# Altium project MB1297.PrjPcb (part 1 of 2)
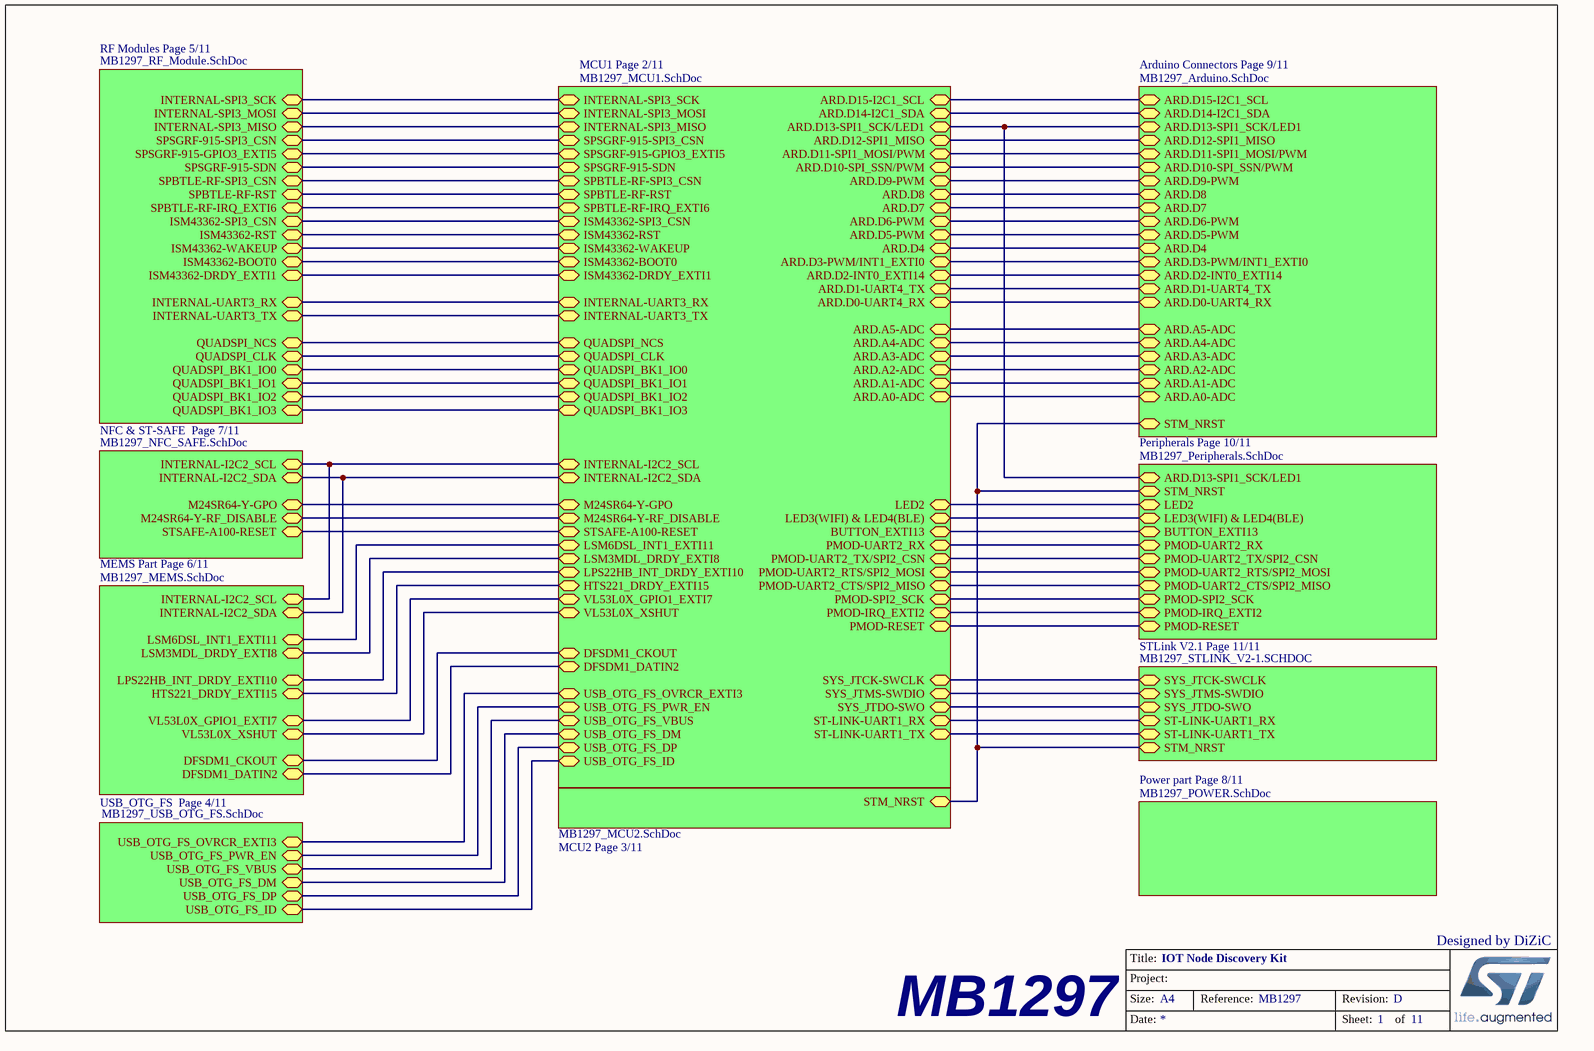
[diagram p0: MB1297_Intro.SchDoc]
11 sheets, 231 parts. Net scope: hierarchical (ports join the sheet entries above them; power ports are global).
Board file: MB1297.PcbDoc
Sheets:
  MB1297_Intro.SchDoc
    MCU1 Page 2/11 = MB1297_MCU1.SchDoc
    MCU2 Page 3/11 = MB1297_MCU2.SchDoc
    RF Modules Page 5/11 = MB1297_RF_Module.SchDoc
    Peripherals Page 10/11 = MB1297_Peripherals.SchDoc
    NFC & ST-SAFE  Page 7/11 = MB1297_NFC_SAFE.SchDoc
    STLink V2.1 Page 11/11 = MB1297_STLINK_V2-1.SCHDOC
    Arduino Connectors Page 9/11 = MB1297_Arduino.SchDoc
    MEMS Part Page 6/11 = MB1297_MEMS.SchDoc
    USB_OTG_FS  Page 4/11 = MB1297_USB_OTG_FS.SchDoc
    Power part Page 8/11 = MB1297_POWER.SchDoc

## Sheet MB1297_Intro.SchDoc: IOT Node Discovery Kit
size A4; DocumentNumber: MB1297; Revision: D; SheetNumber: 1; SheetTotal: 11

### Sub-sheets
Arduino Connectors Page 9/11 = MB1297_Arduino.SchDoc: ARD.D3-PWM/INT1_EXTI0, ARD.D2-INT0_EXTI14, ARD.D1-UART4_TX, ARD.D0-UART4_RX, ARD.A5-ADC, ARD.A4-ADC, ARD.A3-ADC, ARD.A2-ADC, ARD.A1-ADC, ARD.A0-ADC, ARD.D4, ARD.D5-PWM, ARD.D6-PWM, ARD.D7, ARD.D8, ARD.D9-PWM, ARD.D10-SPI_SSN/PWM, ARD.D11-SPI1_MOSI/PWM, ARD.D12-SPI1_MISO, ARD.D13-SPI1_SCK/LED1, ARD.D14-I2C1_SDA, ARD.D15-I2C1_SCL, STM_NRST
MCU1 Page 2/11 = MB1297_MCU1.SchDoc: INTERNAL-SPI3_SCK, INTERNAL-SPI3_MOSI, INTERNAL-SPI3_MISO, ISM43362-SPI3_CSN, SPSGRF-915-SDN, SPSGRF-915-SPI3_CSN, SPBTLE-RF-SPI3_CSN, SYS_JTCK-SWCLK, SYS_JTMS-SWDIO, ARD.D3-PWM/INT1_EXTI0, ARD.D2-INT0_EXTI14, ARD.D1-UART4_TX, ARD.D0-UART4_RX, ARD.D4, ARD.D5-PWM, ARD.D6-PWM, ARD.D7, ARD.D8, ARD.D9-PWM, ARD.D10-SPI_SSN/PWM, ARD.D11-SPI1_MOSI/PWM, ARD.D12-SPI1_MISO, ARD.D13-SPI1_SCK/LED1, ARD.D14-I2C1_SDA, ARD.D15-I2C1_SCL, ARD.A5-ADC, ARD.A4-ADC, ARD.A3-ADC, ARD.A2-ADC, ARD.A1-ADC, ARD.A0-ADC, USB_OTG_FS_OVRCR_EXTI3, USB_OTG_FS_PWR_EN, USB_OTG_FS_VBUS, USB_OTG_FS_DM, USB_OTG_FS_DP, USB_OTG_FS_ID, INTERNAL-I2C2_SCL, INTERNAL-I2C2_SDA, M24SR64-Y-GPO, M24SR64-Y-RF_DISABLE, STSAFE-A100-RESET, LED2, LED3(WIFI) & LED4(BLE), BUTTON_EXTI13, PMOD-UART2_RTS/SPI2_MOSI, PMOD-UART2_CTS/SPI2_MISO, PMOD-SPI2_SCK, PMOD-IRQ_EXTI2, PMOD-RESET, PMOD-UART2_RX, PMOD-UART2_TX/SPI2_CSN, LSM6DSL_INT1_EXTI11, LSM3MDL_DRDY_EXTI8, LPS22HB_INT_DRDY_EXTI10, HTS221_DRDY_EXTI15, VL53L0X_GPIO1_EXTI7, VL53L0X_XSHUT, DFSDM1_CKOUT, DFSDM1_DATIN2, SPBTLE-RF-RST, SYS_JTDO-SWO, QUADSPI_NCS, QUADSPI_CLK, QUADSPI_BK1_IO0, QUADSPI_BK1_IO1, QUADSPI_BK1_IO2, QUADSPI_BK1_IO3, SPSGRF-915-GPIO3_EXTI5, SPBTLE-RF-IRQ_EXTI6, ISM43362-DRDY_EXTI1, ISM43362-RST, ISM43362-WAKEUP, ISM43362-BOOT0, INTERNAL-UART3_RX, INTERNAL-UART3_TX, ST-LINK-UART1_RX, ST-LINK-UART1_TX
MCU2 Page 3/11 = MB1297_MCU2.SchDoc: STM_NRST
MEMS Part Page 6/11 = MB1297_MEMS.SchDoc: INTERNAL-I2C2_SCL, INTERNAL-I2C2_SDA, LSM6DSL_INT1_EXTI11, LSM3MDL_DRDY_EXTI8, LPS22HB_INT_DRDY_EXTI10, HTS221_DRDY_EXTI15, VL53L0X_GPIO1_EXTI7, VL53L0X_XSHUT, DFSDM1_CKOUT, DFSDM1_DATIN2
NFC & ST-SAFE  Page 7/11 = MB1297_NFC_SAFE.SchDoc: INTERNAL-I2C2_SCL, INTERNAL-I2C2_SDA, M24SR64-Y-GPO, M24SR64-Y-RF_DISABLE, STSAFE-A100-RESET
Peripherals Page 10/11 = MB1297_Peripherals.SchDoc: STM_NRST, ARD.D13-SPI1_SCK/LED1, LED2, LED3(WIFI) & LED4(BLE), BUTTON_EXTI13, PMOD-UART2_RTS/SPI2_MOSI, PMOD-UART2_CTS/SPI2_MISO, PMOD-SPI2_SCK, PMOD-IRQ_EXTI2, PMOD-RESET, PMOD-UART2_RX, PMOD-UART2_TX/SPI2_CSN
Power part Page 8/11 = MB1297_POWER.SchDoc: no entries
RF Modules Page 5/11 = MB1297_RF_Module.SchDoc: INTERNAL-SPI3_SCK, INTERNAL-SPI3_MOSI, INTERNAL-SPI3_MISO, SPSGRF-915-SPI3_CSN, SPSGRF-915-GPIO3_EXTI5, SPSGRF-915-SDN, SPBTLE-RF-SPI3_CSN, SPBTLE-RF-RST, SPBTLE-RF-IRQ_EXTI6, QUADSPI_NCS, QUADSPI_CLK, QUADSPI_BK1_IO0, QUADSPI_BK1_IO1, QUADSPI_BK1_IO2, QUADSPI_BK1_IO3, INTERNAL-UART3_RX, INTERNAL-UART3_TX, ISM43362-SPI3_CSN, ISM43362-RST, ISM43362-WAKEUP, ISM43362-BOOT0, ISM43362-DRDY_EXTI1
STLink V2.1 Page 11/11 = MB1297_STLINK_V2-1.SCHDOC: SYS_JTCK-SWCLK, SYS_JTMS-SWDIO, SYS_JTDO-SWO, ST-LINK-UART1_RX, ST-LINK-UART1_TX, STM_NRST
USB_OTG_FS  Page 4/11 = MB1297_USB_OTG_FS.SchDoc: USB_OTG_FS_OVRCR_EXTI3, USB_OTG_FS_PWR_EN, USB_OTG_FS_VBUS, USB_OTG_FS_DM, USB_OTG_FS_DP, USB_OTG_FS_ID

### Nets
USB_N: sheet MCU1 Page 2/11/USB_OTG_FS_DM, sheet USB_OTG_FS  Page 4/11/USB_OTG_FS_DM
USB_P: sheet MCU1 Page 2/11/USB_OTG_FS_DP, sheet USB_OTG_FS  Page 4/11/USB_OTG_FS_DP
NetC3_2: sheet MCU2 Page 3/11/STM_NRST, sheet Peripherals Page 10/11/STM_NRST, sheet STLink V2.1 Page 11/11/STM_NRST, sheet Arduino Connectors Page 9/11/STM_NRST
NetC66_1: sheet MCU1 Page 2/11/USB_OTG_FS_VBUS, sheet USB_OTG_FS  Page 4/11/USB_OTG_FS_VBUS
NetCN1_1: sheet MCU1 Page 2/11/ARD.D8, sheet Arduino Connectors Page 9/11/ARD.D8
NetCN1_2: sheet MCU1 Page 2/11/ARD.D9-PWM, sheet Arduino Connectors Page 9/11/ARD.D9-PWM
NetCN1_3: sheet MCU1 Page 2/11/ARD.D10-SPI_SSN/PWM, sheet Arduino Connectors Page 9/11/ARD.D10-SPI_SSN/PWM
NetCN1_4: sheet MCU1 Page 2/11/ARD.D11-SPI1_MOSI/PWM, sheet Arduino Connectors Page 9/11/ARD.D11-SPI1_MOSI/PWM
NetCN1_5: sheet MCU1 Page 2/11/ARD.D12-SPI1_MISO, sheet Arduino Connectors Page 9/11/ARD.D12-SPI1_MISO
NetCN1_6: sheet MCU1 Page 2/11/ARD.D13-SPI1_SCK/LED1, sheet Peripherals Page 10/11/ARD.D13-SPI1_SCK/LED1, sheet Arduino Connectors Page 9/11/ARD.D13-SPI1_SCK/LED1
NetCN1_9: sheet MCU1 Page 2/11/ARD.D14-I2C1_SDA, sheet Arduino Connectors Page 9/11/ARD.D14-I2C1_SDA
NetCN1_10: sheet MCU1 Page 2/11/ARD.D15-I2C1_SCL, sheet Arduino Connectors Page 9/11/ARD.D15-I2C1_SCL
NetCN3_1: sheet MCU1 Page 2/11/ARD.D0-UART4_RX, sheet Arduino Connectors Page 9/11/ARD.D0-UART4_RX
NetCN3_2: sheet MCU1 Page 2/11/ARD.D1-UART4_TX, sheet Arduino Connectors Page 9/11/ARD.D1-UART4_TX
NetCN3_3: sheet MCU1 Page 2/11/ARD.D2-INT0_EXTI14, sheet Arduino Connectors Page 9/11/ARD.D2-INT0_EXTI14
NetCN3_4: sheet MCU1 Page 2/11/ARD.D3-PWM/INT1_EXTI0, sheet Arduino Connectors Page 9/11/ARD.D3-PWM/INT1_EXTI0
NetCN3_5: sheet MCU1 Page 2/11/ARD.D4, sheet Arduino Connectors Page 9/11/ARD.D4
NetCN3_6: sheet MCU1 Page 2/11/ARD.D5-PWM, sheet Arduino Connectors Page 9/11/ARD.D5-PWM
NetCN3_7: sheet MCU1 Page 2/11/ARD.D6-PWM, sheet Arduino Connectors Page 9/11/ARD.D6-PWM
NetCN3_8: sheet MCU1 Page 2/11/ARD.D7, sheet Arduino Connectors Page 9/11/ARD.D7
NetCN4_1: sheet MCU1 Page 2/11/ARD.A0-ADC, sheet Arduino Connectors Page 9/11/ARD.A0-ADC
NetCN4_2: sheet MCU1 Page 2/11/ARD.A1-ADC, sheet Arduino Connectors Page 9/11/ARD.A1-ADC
NetCN4_3: sheet MCU1 Page 2/11/ARD.A2-ADC, sheet Arduino Connectors Page 9/11/ARD.A2-ADC
NetCN4_4: sheet MCU1 Page 2/11/ARD.A3-ADC, sheet Arduino Connectors Page 9/11/ARD.A3-ADC
NetCN4_5: sheet MCU1 Page 2/11/ARD.A4-ADC, sheet Arduino Connectors Page 9/11/ARD.A4-ADC
NetCN4_6: sheet MCU1 Page 2/11/ARD.A5-ADC, sheet Arduino Connectors Page 9/11/ARD.A5-ADC
NetCN9_4: sheet MCU1 Page 2/11/USB_OTG_FS_ID, sheet USB_OTG_FS  Page 4/11/USB_OTG_FS_ID
NetCN10_7: sheet MCU1 Page 2/11/PMOD-IRQ_EXTI2, sheet Peripherals Page 10/11/PMOD-IRQ_EXTI2
NetCN10_8: sheet MCU1 Page 2/11/PMOD-RESET, sheet Peripherals Page 10/11/PMOD-RESET
NetM1_4: sheet MCU1 Page 2/11/SPBTLE-RF-IRQ_EXTI6, sheet RF Modules Page 5/11/SPBTLE-RF-IRQ_EXTI6
NetM1_7: sheet MCU1 Page 2/11/INTERNAL-SPI3_SCK, sheet RF Modules Page 5/11/INTERNAL-SPI3_SCK
NetM1_8: sheet MCU1 Page 2/11/INTERNAL-SPI3_MISO, sheet RF Modules Page 5/11/INTERNAL-SPI3_MISO
NetM1_9: sheet MCU1 Page 2/11/INTERNAL-SPI3_MOSI, sheet RF Modules Page 5/11/INTERNAL-SPI3_MOSI
NetM1_10: sheet MCU1 Page 2/11/SPBTLE-RF-SPI3_CSN, sheet RF Modules Page 5/11/SPBTLE-RF-SPI3_CSN
NetM1_11: sheet MCU1 Page 2/11/SPBTLE-RF-RST, sheet RF Modules Page 5/11/SPBTLE-RF-RST
NetM2_12: sheet MCU1 Page 2/11/ISM43362-SPI3_CSN, sheet RF Modules Page 5/11/ISM43362-SPI3_CSN
NetM2_13: sheet MCU1 Page 2/11/ISM43362-DRDY_EXTI1, sheet RF Modules Page 5/11/ISM43362-DRDY_EXTI1
NetM2_16: sheet MCU1 Page 2/11/ISM43362-WAKEUP, sheet RF Modules Page 5/11/ISM43362-WAKEUP
NetM2_21: sheet MCU1 Page 2/11/INTERNAL-UART3_TX, sheet RF Modules Page 5/11/INTERNAL-UART3_TX
NetM2_22: sheet MCU1 Page 2/11/INTERNAL-UART3_RX, sheet RF Modules Page 5/11/INTERNAL-UART3_RX
NetM2_33: sheet MCU1 Page 2/11/ISM43362-BOOT0, sheet RF Modules Page 5/11/ISM43362-BOOT0
NetM2_34: sheet MCU1 Page 2/11/ISM43362-RST, sheet RF Modules Page 5/11/ISM43362-RST
NetM3_1: sheet MCU1 Page 2/11/SPSGRF-915-GPIO3_EXTI5, sheet RF Modules Page 5/11/SPSGRF-915-GPIO3_EXTI5
NetM3_10: sheet MCU1 Page 2/11/SPSGRF-915-SPI3_CSN, sheet RF Modules Page 5/11/SPSGRF-915-SPI3_CSN
NetM3_11: sheet MCU1 Page 2/11/SPSGRF-915-SDN, sheet RF Modules Page 5/11/SPSGRF-915-SDN
NetR1_2: sheet MCU1 Page 2/11/M24SR64-Y-RF_DISABLE, sheet NFC & ST-SAFE  Page 7/11/M24SR64-Y-RF_DISABLE
NetR4_2: sheet MCU1 Page 2/11/M24SR64-Y-GPO, sheet NFC & ST-SAFE  Page 7/11/M24SR64-Y-GPO
NetR6_2: sheet MCU1 Page 2/11/DFSDM1_CKOUT, sheet MEMS Part Page 6/11/DFSDM1_CKOUT
NetR10_2: sheet MCU1 Page 2/11/INTERNAL-I2C2_SCL, sheet NFC & ST-SAFE  Page 7/11/INTERNAL-I2C2_SCL, sheet MEMS Part Page 6/11/INTERNAL-I2C2_SCL
NetR11_2: sheet MCU1 Page 2/11/INTERNAL-I2C2_SDA, sheet NFC & ST-SAFE  Page 7/11/INTERNAL-I2C2_SDA, sheet MEMS Part Page 6/11/INTERNAL-I2C2_SDA
NetR13_2: sheet MCU1 Page 2/11/DFSDM1_DATIN2, sheet MEMS Part Page 6/11/DFSDM1_DATIN2
NetR14_2: sheet MCU1 Page 2/11/VL53L0X_GPIO1_EXTI7, sheet MEMS Part Page 6/11/VL53L0X_GPIO1_EXTI7
NetR15_2: sheet MCU1 Page 2/11/VL53L0X_XSHUT, sheet MEMS Part Page 6/11/VL53L0X_XSHUT
NetR20_1: sheet MCU1 Page 2/11/LED2, sheet Peripherals Page 10/11/LED2
NetR21_1: sheet MCU1 Page 2/11/LED3(WIFI) & LED4(BLE), sheet Peripherals Page 10/11/LED3(WIFI) & LED4(BLE)
NetR32_2: sheet MCU1 Page 2/11/SYS_JTCK-SWCLK, sheet STLink V2.1 Page 11/11/SYS_JTCK-SWCLK
NetR33_2: sheet MCU1 Page 2/11/SYS_JTMS-SWDIO, sheet STLink V2.1 Page 11/11/SYS_JTMS-SWDIO
NetR35_2: sheet MCU1 Page 2/11/SYS_JTDO-SWO, sheet STLink V2.1 Page 11/11/SYS_JTDO-SWO
NetR42_2: sheet MCU1 Page 2/11/ST-LINK-UART1_RX, sheet STLink V2.1 Page 11/11/ST-LINK-UART1_RX
NetR43_2: sheet MCU1 Page 2/11/ST-LINK-UART1_TX, sheet STLink V2.1 Page 11/11/ST-LINK-UART1_TX
NetR56_1: sheet MCU1 Page 2/11/USB_OTG_FS_OVRCR_EXTI3, sheet USB_OTG_FS  Page 4/11/USB_OTG_FS_OVRCR_EXTI3
NetR62_2: sheet MCU1 Page 2/11/USB_OTG_FS_PWR_EN, sheet USB_OTG_FS  Page 4/11/USB_OTG_FS_PWR_EN
NetSB3_1: sheet MCU1 Page 2/11/BUTTON_EXTI13, sheet Peripherals Page 10/11/BUTTON_EXTI13
NetSB12_2: sheet MCU1 Page 2/11/PMOD-UART2_TX/SPI2_CSN, sheet Peripherals Page 10/11/PMOD-UART2_TX/SPI2_CSN
NetSB15_2: sheet MCU1 Page 2/11/PMOD-UART2_RTS/SPI2_MOSI, sheet Peripherals Page 10/11/PMOD-UART2_RTS/SPI2_MOSI
NetSB18_2: sheet MCU1 Page 2/11/PMOD-UART2_CTS/SPI2_MISO, sheet Peripherals Page 10/11/PMOD-UART2_CTS/SPI2_MISO
NetSB20_1: sheet MCU1 Page 2/11/PMOD-UART2_RX, sheet Peripherals Page 10/11/PMOD-UART2_RX
NetSB21_1: sheet MCU1 Page 2/11/PMOD-SPI2_SCK, sheet Peripherals Page 10/11/PMOD-SPI2_SCK
NetU1_41: sheet MCU1 Page 2/11/QUADSPI_CLK, sheet RF Modules Page 5/11/QUADSPI_CLK
NetU1_42: sheet MCU1 Page 2/11/QUADSPI_NCS, sheet RF Modules Page 5/11/QUADSPI_NCS
NetU1_43: sheet MCU1 Page 2/11/QUADSPI_BK1_IO0, sheet RF Modules Page 5/11/QUADSPI_BK1_IO0
NetU1_44: sheet MCU1 Page 2/11/QUADSPI_BK1_IO1, sheet RF Modules Page 5/11/QUADSPI_BK1_IO1
NetU1_45: sheet MCU1 Page 2/11/QUADSPI_BK1_IO2, sheet RF Modules Page 5/11/QUADSPI_BK1_IO2
NetU1_46: sheet MCU1 Page 2/11/QUADSPI_BK1_IO3, sheet RF Modules Page 5/11/QUADSPI_BK1_IO3
NetU1_57: sheet MCU1 Page 2/11/LPS22HB_INT_DRDY_EXTI10, sheet MEMS Part Page 6/11/LPS22HB_INT_DRDY_EXTI10
NetU1_58: sheet MCU1 Page 2/11/LSM6DSL_INT1_EXTI11, sheet MEMS Part Page 6/11/LSM6DSL_INT1_EXTI11
NetU1_62: sheet MCU1 Page 2/11/HTS221_DRDY_EXTI15, sheet MEMS Part Page 6/11/HTS221_DRDY_EXTI15
NetU1_65: sheet MCU1 Page 2/11/LSM3MDL_DRDY_EXTI8, sheet MEMS Part Page 6/11/LSM3MDL_DRDY_EXTI8
NetU1_88: sheet MCU1 Page 2/11/STSAFE-A100-RESET, sheet NFC & ST-SAFE  Page 7/11/STSAFE-A100-RESET

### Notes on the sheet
- Designed by DiZiC
- MB1297

## Sheet MB1297_MCU1.SchDoc: STM32L475 - 1/2
size A4; DocumentNumber: MB1297; Revision: D; SheetNumber: 2; SheetTotal: 11
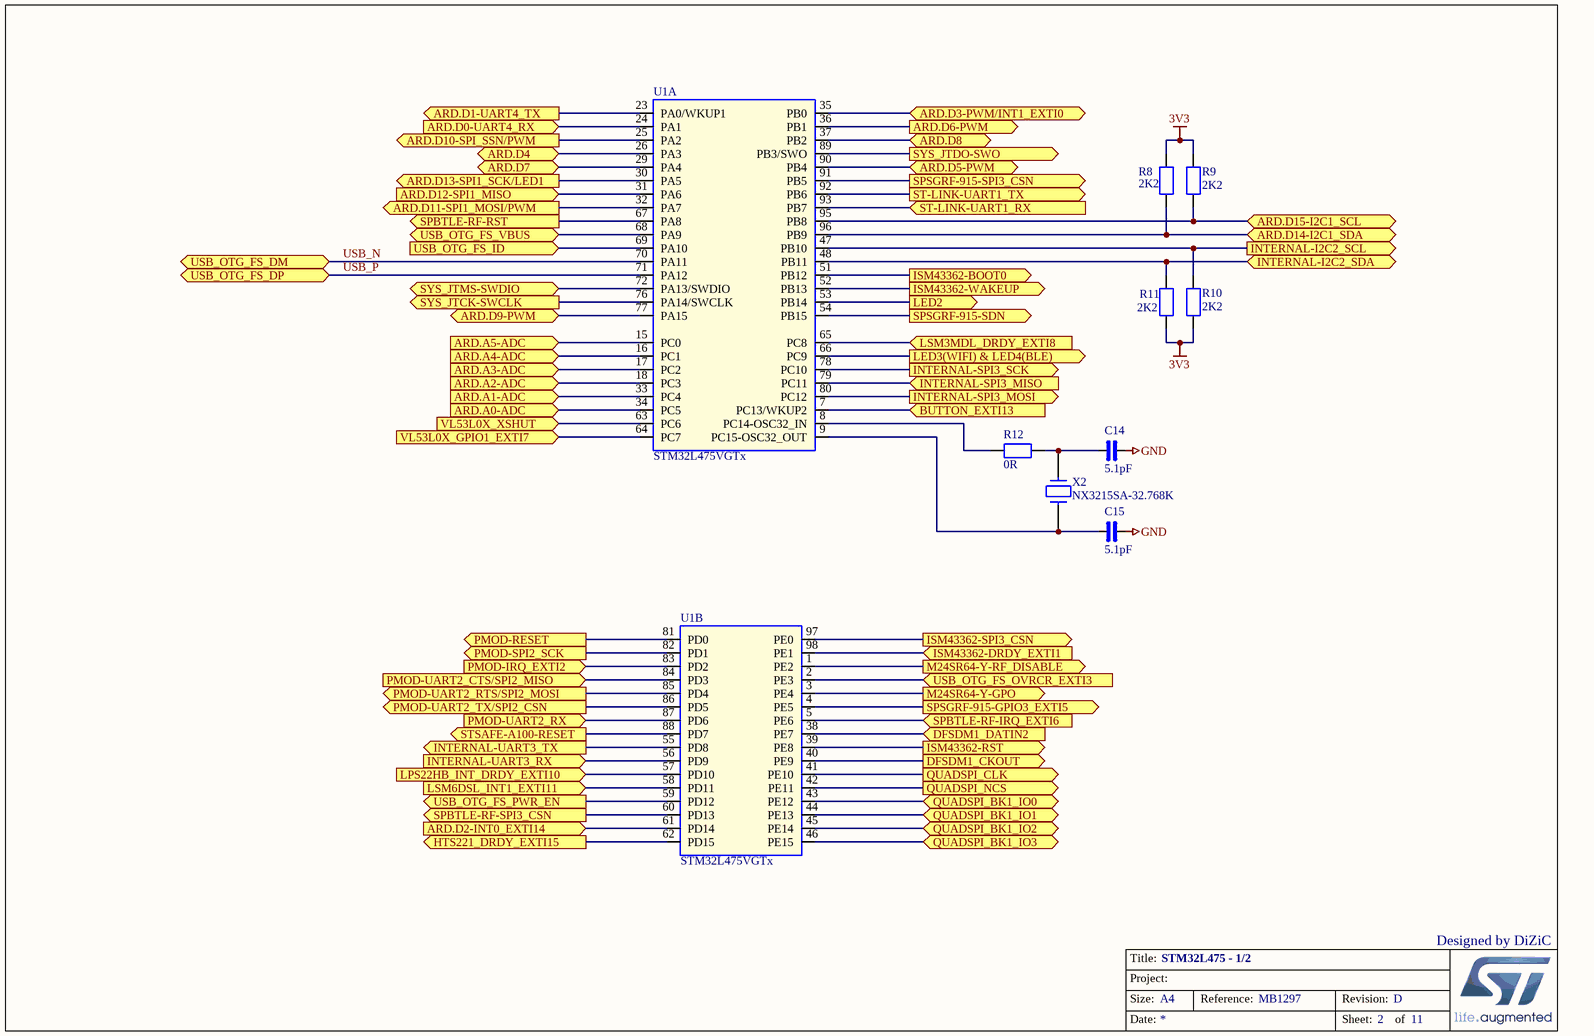
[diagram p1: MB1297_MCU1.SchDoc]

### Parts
C14  5.1pF  [0402_CAP_NPOL]
C15  5.1pF  [0402_CAP_NPOL]
R8  2K2  [0402_RES]
R9  2K2  [0402_RES]
R10  2K2  [0402_RES]
R11  2K2  [0402_RES]
R12  0R  [0402_RES]
U1  STM32L475VGTx  [LQFP100 14x14x1.6]  (parts A,B of 3)
X2  NX3215SA-32.768K  [CRY_NX3215SA_2P]

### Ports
ARD.A0-ADC, ARD.A1-ADC, ARD.A2-ADC, ARD.A3-ADC, ARD.A4-ADC, ARD.A5-ADC, ARD.D0-UART4_RX, ARD.D1-UART4_TX, ARD.D2-INT0_EXTI14, ARD.D3-PWM/INT1_EXTI0, ARD.D4, ARD.D5-PWM, ARD.D6-PWM, ARD.D7, ARD.D8, ARD.D9-PWM, ARD.D10-SPI_SSN/PWM, ARD.D11-SPI1_MOSI/PWM, ARD.D12-SPI1_MISO, ARD.D13-SPI1_SCK/LED1, ARD.D14-I2C1_SDA, ARD.D15-I2C1_SCL, BUTTON_EXTI13, DFSDM1_CKOUT, DFSDM1_DATIN2, HTS221_DRDY_EXTI15, INTERNAL-I2C2_SCL, INTERNAL-I2C2_SDA, INTERNAL-SPI3_MISO, INTERNAL-SPI3_MOSI, INTERNAL-SPI3_SCK, INTERNAL-UART3_RX, INTERNAL-UART3_TX, ISM43362-BOOT0, ISM43362-DRDY_EXTI1, ISM43362-RST, ISM43362-SPI3_CSN, ISM43362-WAKEUP, LED2, LED3(WIFI) & LED4(BLE), LPS22HB_INT_DRDY_EXTI10, LSM3MDL_DRDY_EXTI8, LSM6DSL_INT1_EXTI11, M24SR64-Y-GPO, M24SR64-Y-RF_DISABLE, PMOD-IRQ_EXTI2, PMOD-RESET, PMOD-SPI2_SCK, PMOD-UART2_CTS/SPI2_MISO, PMOD-UART2_RTS/SPI2_MOSI, PMOD-UART2_RX, PMOD-UART2_TX/SPI2_CSN, QUADSPI_BK1_IO0, QUADSPI_BK1_IO1, QUADSPI_BK1_IO2, QUADSPI_BK1_IO3, QUADSPI_CLK, QUADSPI_NCS, SPBTLE-RF-IRQ_EXTI6, SPBTLE-RF-RST, SPBTLE-RF-SPI3_CSN, SPSGRF-915-GPIO3_EXTI5, SPSGRF-915-SDN, SPSGRF-915-SPI3_CSN, ST-LINK-UART1_RX, ST-LINK-UART1_TX, STSAFE-A100-RESET, SYS_JTCK-SWCLK, SYS_JTDO-SWO, SYS_JTMS-SWDIO, USB_OTG_FS_DM, USB_OTG_FS_DP, USB_OTG_FS_ID, USB_OTG_FS_OVRCR_EXTI3, USB_OTG_FS_PWR_EN, USB_OTG_FS_VBUS, VL53L0X_GPIO1_EXTI7, VL53L0X_XSHUT

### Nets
3V3: R8.1 R9.1 R10.1 R11.1
GND: C14.2 C15.2
USB_N: U1.70(PA11) ; port USB_OTG_FS_DM
USB_P: U1.71(PA12) ; port USB_OTG_FS_DP
NetC14_1: C14.1 R12.2 X2.1
NetC15_1: C15.1 U1.9(PC15-OSC32_OUT) X2.2
NetC66_1: U1.68(PA9) ; port USB_OTG_FS_VBUS
NetCN1_1: U1.37(PB2) ; port ARD.D8
NetCN1_2: U1.77(PA15) ; port ARD.D9-PWM
NetCN1_3: U1.25(PA2) ; port ARD.D10-SPI_SSN/PWM
NetCN1_4: U1.32(PA7) ; port ARD.D11-SPI1_MOSI/PWM
NetCN1_5: U1.31(PA6) ; port ARD.D12-SPI1_MISO
NetCN1_6: U1.30(PA5) ; port ARD.D13-SPI1_SCK/LED1
NetCN1_9: R8.2 U1.96(PB9) ; port ARD.D14-I2C1_SDA
NetCN1_10: R9.2 U1.95(PB8) ; port ARD.D15-I2C1_SCL
NetCN3_1: U1.24(PA1) ; port ARD.D0-UART4_RX
NetCN3_2: U1.23(PA0/WKUP1) ; port ARD.D1-UART4_TX
NetCN3_3: U1.61(PD14) ; port ARD.D2-INT0_EXTI14
NetCN3_4: U1.35(PB0) ; port ARD.D3-PWM/INT1_EXTI0
NetCN3_5: U1.26(PA3) ; port ARD.D4
NetCN3_6: U1.90(PB4) ; port ARD.D5-PWM
NetCN3_7: U1.36(PB1) ; port ARD.D6-PWM
NetCN3_8: U1.29(PA4) ; port ARD.D7
NetCN4_1: U1.34(PC5) ; port ARD.A0-ADC
NetCN4_2: U1.33(PC4) ; port ARD.A1-ADC
NetCN4_3: U1.18(PC3) ; port ARD.A2-ADC
NetCN4_4: U1.17(PC2) ; port ARD.A3-ADC
NetCN4_5: U1.16(PC1) ; port ARD.A4-ADC
NetCN4_6: U1.15(PC0) ; port ARD.A5-ADC
NetCN9_4: U1.69(PA10) ; port USB_OTG_FS_ID
NetCN10_7: U1.83(PD2) ; port PMOD-IRQ_EXTI2
NetCN10_8: U1.81(PD0) ; port PMOD-RESET
NetM1_4: U1.5(PE6) ; port SPBTLE-RF-IRQ_EXTI6
NetM1_7: U1.78(PC10) ; port INTERNAL-SPI3_SCK
NetM1_8: U1.79(PC11) ; port INTERNAL-SPI3_MISO
NetM1_9: U1.80(PC12) ; port INTERNAL-SPI3_MOSI
NetM1_10: U1.60(PD13) ; port SPBTLE-RF-SPI3_CSN
NetM1_11: U1.67(PA8) ; port SPBTLE-RF-RST
NetM2_12: U1.97(PE0) ; port ISM43362-SPI3_CSN
NetM2_13: U1.98(PE1) ; port ISM43362-DRDY_EXTI1
NetM2_16: U1.52(PB13) ; port ISM43362-WAKEUP
NetM2_21: U1.55(PD8) ; port INTERNAL-UART3_TX
NetM2_22: U1.56(PD9) ; port INTERNAL-UART3_RX
NetM2_33: U1.51(PB12) ; port ISM43362-BOOT0
NetM2_34: U1.39(PE8) ; port ISM43362-RST
NetM3_1: U1.4(PE5) ; port SPSGRF-915-GPIO3_EXTI5
NetM3_10: U1.91(PB5) ; port SPSGRF-915-SPI3_CSN
NetM3_11: U1.54(PB15) ; port SPSGRF-915-SDN
NetR1_2: U1.1(PE2) ; port M24SR64-Y-RF_DISABLE
NetR4_2: U1.3(PE4) ; port M24SR64-Y-GPO
NetR6_2: U1.40(PE9) ; port DFSDM1_CKOUT
NetR10_2: R10.2 U1.47(PB10) ; port INTERNAL-I2C2_SCL
NetR11_2: R11.2 U1.48(PB11) ; port INTERNAL-I2C2_SDA
NetR12_1: R12.1 U1.8(PC14-OSC32_IN)
NetR13_2: U1.38(PE7) ; port DFSDM1_DATIN2
NetR14_2: U1.64(PC7) ; port VL53L0X_GPIO1_EXTI7
NetR15_2: U1.63(PC6) ; port VL53L0X_XSHUT
NetR20_1: U1.53(PB14) ; port LED2
NetR21_1: U1.66(PC9) ; port LED3(WIFI) & LED4(BLE)
NetR32_2: U1.76(PA14/SWCLK) ; port SYS_JTCK-SWCLK
NetR33_2: U1.72(PA13/SWDIO) ; port SYS_JTMS-SWDIO
NetR35_2: U1.89(PB3/SWO) ; port SYS_JTDO-SWO
NetR42_2: U1.93(PB7) ; port ST-LINK-UART1_RX
NetR43_2: U1.92(PB6) ; port ST-LINK-UART1_TX
NetR56_1: U1.2(PE3) ; port USB_OTG_FS_OVRCR_EXTI3
NetR62_2: U1.59(PD12) ; port USB_OTG_FS_PWR_EN
NetSB3_1: U1.7(PC13/WKUP2) ; port BUTTON_EXTI13
NetSB12_2: U1.86(PD5) ; port PMOD-UART2_TX/SPI2_CSN
NetSB15_2: U1.85(PD4) ; port PMOD-UART2_RTS/SPI2_MOSI
NetSB18_2: U1.84(PD3) ; port PMOD-UART2_CTS/SPI2_MISO
NetSB20_1: U1.87(PD6) ; port PMOD-UART2_RX
NetSB21_1: U1.82(PD1) ; port PMOD-SPI2_SCK
NetU1_41: U1.41(PE10) ; port QUADSPI_CLK
NetU1_42: U1.42(PE11) ; port QUADSPI_NCS
NetU1_43: U1.43(PE12) ; port QUADSPI_BK1_IO0
NetU1_44: U1.44(PE13) ; port QUADSPI_BK1_IO1
NetU1_45: U1.45(PE14) ; port QUADSPI_BK1_IO2
NetU1_46: U1.46(PE15) ; port QUADSPI_BK1_IO3
NetU1_57: U1.57(PD10) ; port LPS22HB_INT_DRDY_EXTI10
NetU1_58: U1.58(PD11) ; port LSM6DSL_INT1_EXTI11
NetU1_62: U1.62(PD15) ; port HTS221_DRDY_EXTI15
NetU1_65: U1.65(PC8) ; port LSM3MDL_DRDY_EXTI8
NetU1_88: U1.88(PD7) ; port STSAFE-A100-RESET

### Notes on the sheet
- Designed by DiZiC

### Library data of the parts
C14 C15 = CAP_NPOL: Capacitor_not polarized
R8-R12 = RES: Resistor
X2 = XTAL_32K_NX3215SA: Crystal 32.768kHz, 6pF, -+20PPM, R=50K, SMD; Manuf_1: NDK; Manuf_Part_1: NX3215SA 32.768KHz EXS00A-MU00525; ECCN_US/EU: EAR99/NEC; Ref St: 9157034; NDK Ref: X3101802; Fitted: YES; Ordered_By: STM

## Sheet MB1297_MCU2.SchDoc: STM32L475 - 2/2
size A4; DocumentNumber: MB1297; Revision: D; SheetNumber: 3; SheetTotal: 11
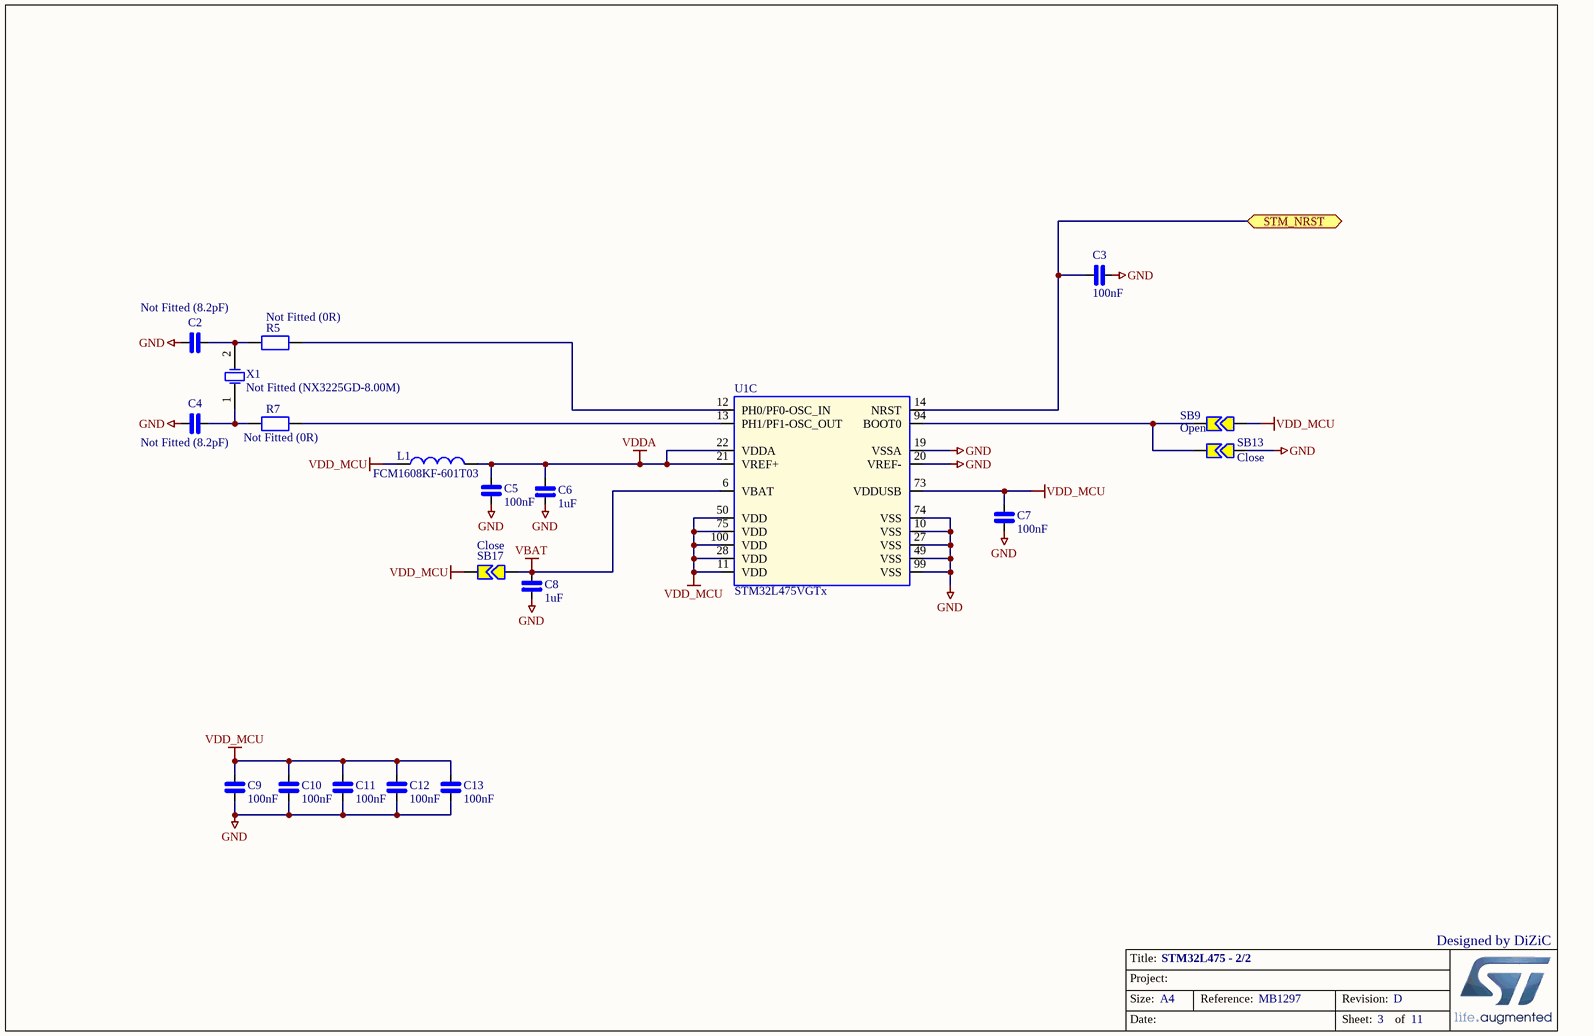
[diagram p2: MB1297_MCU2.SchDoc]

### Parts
C2  Not Fitted (8.2pF)  [0402_CAP_NPOL]
C3  100nF  [0402_CAP_NPOL]
C4  Not Fitted (8.2pF)  [0402_CAP_NPOL]
C5  100nF  [0402_CAP_NPOL]
C6  1uF  [0402_CAP_NPOL]
C7  100nF  [0402_CAP_NPOL]
C8  1uF  [0402_CAP_NPOL]
C9  100nF  [0402_CAP_NPOL]
C10  100nF  [0402_CAP_NPOL]
C11  100nF  [0402_CAP_NPOL]
C12  100nF  [0402_CAP_NPOL]
C13  100nF  [0402_CAP_NPOL]
L1  FCM1608KF-601T03  [0603L]
R5  Not Fitted (0R)  [0402_RES]
R7  Not Fitted (0R)  [0402_RES]
SB9  Open  [SB]
SB13  Close  [SB]
SB17  Close  [SB]
U1  STM32L475VGTx  [LQFP100 14x14x1.6]  (part C of 3)
X1  Not Fitted (NX3225GD-8.00M)  [CRY_NX3225GD_2P]

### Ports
STM_NRST

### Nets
GND: C2.2 C3.1 C4.2 C5.2 C6.1 C7.2 C8.1 C9.2 C10.2 C11.2 C12.2 C13.2 SB13.1 U1.10(VSS) U1.19(VSSA) U1.20(VREF-) U1.27(VSS) U1.49(VSS) U1.74(VSS) U1.99(VSS)
VBAT: C8.2 SB17.2 U1.6(VBAT)
VDD_MCU: C7.1 C9.1 C10.1 C11.1 C12.1 C13.1 L1.1 SB9.1 SB17.1 U1.11(VDD) U1.28(VDD) U1.50(VDD) U1.73(VDDUSB) U1.75(VDD) U1.100(VDD)
VDDA: C5.1 C6.2 L1.2 U1.21(VREF+) U1.22(VDDA)
NetC2_1: C2.1 R5.2 X1.2(OSC2)
NetC3_2: C3.2 U1.14(NRST) ; port STM_NRST
NetC4_1: C4.1 R7.2 X1.1(OSC1)
NetR5_1: R5.1 U1.12(PH0/PF0-OSC_IN)
NetR7_1: R7.1 U1.13(PH1/PF1-OSC_OUT)
NetSB9_2: SB9.2 SB13.2 U1.94(BOOT0)

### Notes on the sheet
- Designed by DiZiC

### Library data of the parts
C2-C13 = CAP_NPOL: Capacitor_not polarized
L1 = Inductor: Value: 100uH
R5 R7 = RES: Resistor; FITTED: NO
SB9 SB13 SB17 = Strap2: Solder Jumper; Solder: YES
X1 = XTAL_8M_NX3225GD: Crystal 8Mhz, 8pF, -+50PPM, SMD; Manuf_1: NDK; Manuf_Part_1: NX3225GD 8MHz EXS00A-CG04874; ECCN_US/EU: EAR99/NEC; NDK Ref: X3127326; Ref St: 9157029; Fitted: NO; Ordered_By: STM

## Sheet MB1297_RF_Module.SchDoc: RF Modules
size A4; DocumentNumber: MB1297; Revision: D; SheetNumber: 5; SheetTotal: 11
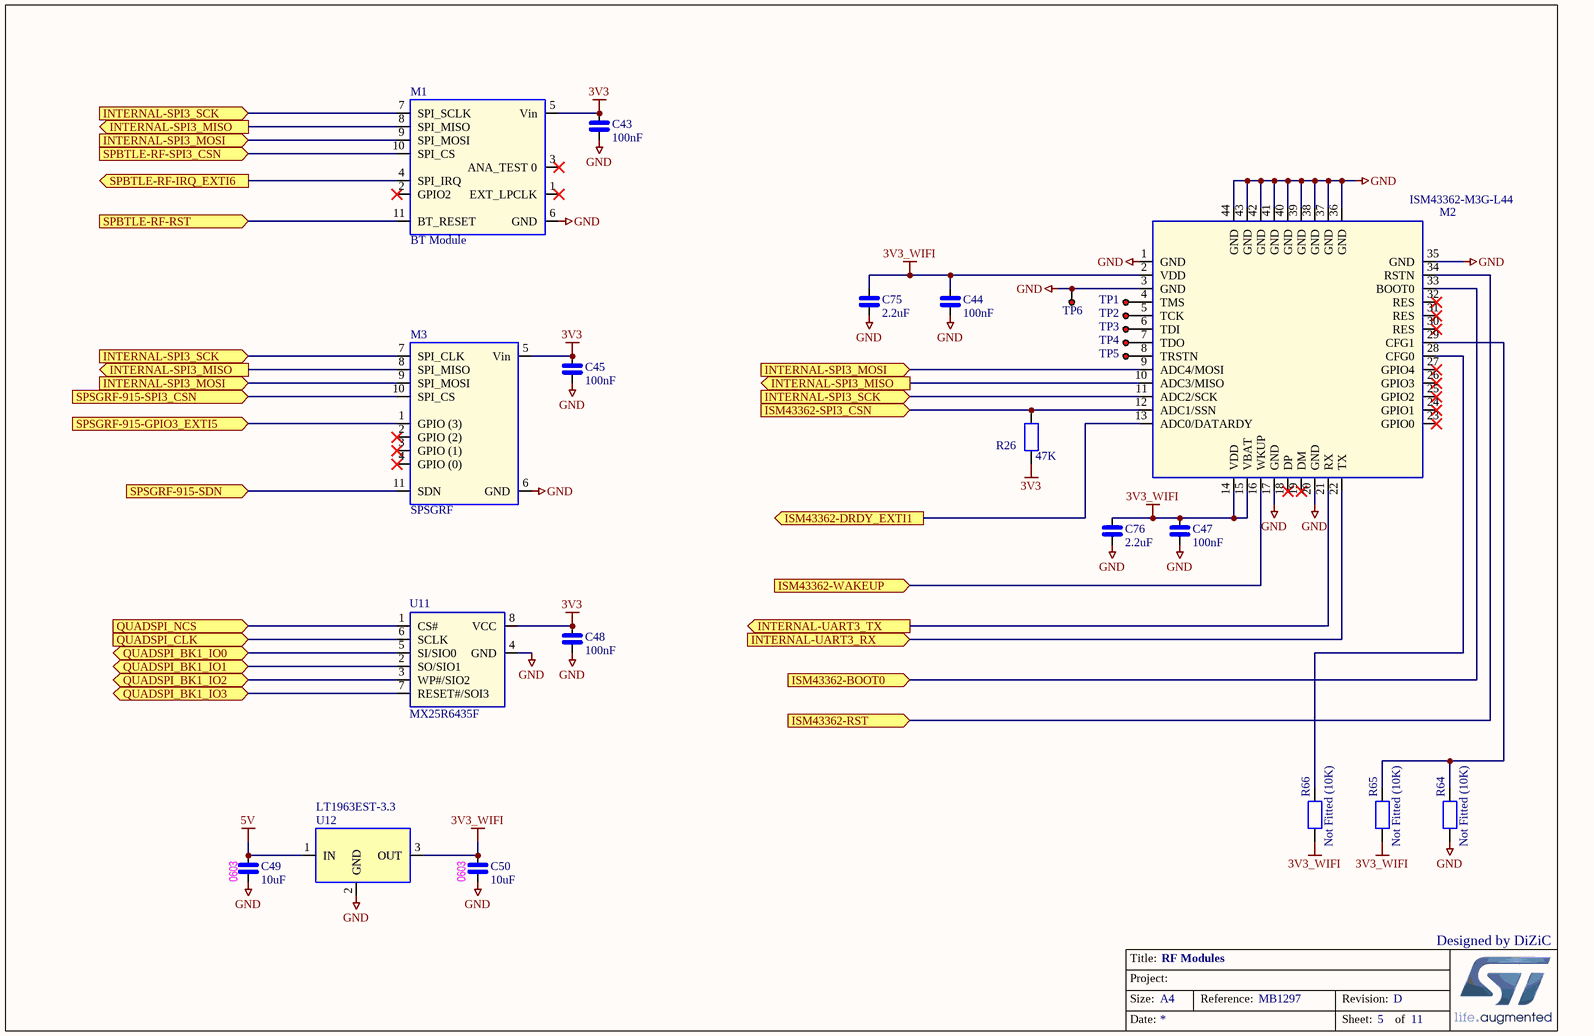
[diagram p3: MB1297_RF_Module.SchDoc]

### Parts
C43  100nF  [0402_CAP_NPOL]
C44  100nF  [0402_CAP_NPOL]
C45  100nF  [0402_CAP_NPOL]
C47  100nF  [0402_CAP_NPOL]
C48  100nF  [0402_CAP_NPOL]
C49  10uF  [0603_CAP_NPOL]
C50  10uF  [0603_CAP_NPOL]
C75  2.2uF  [0603_CAP_NPOL]
C76  2.2uF  [0603_CAP_NPOL]
M1  BT Module  [SPBTLE-RF]
M2  ISM43362-M3G-L44  [ISM43362-M3G-L44]
M3  SPSGRF  [SPSGRF]
R26  47K  [0402_RES]
R64  Not Fitted (10K)  [0402_RES]
R65  Not Fitted (10K)  [0402_RES]
R66  Not Fitted (10K)  [0402_RES]
TP1  PT  [PTB]  (value not drawn)
TP2  PT  [PTB]  (value not drawn)
TP3  PT  [PTB]  (value not drawn)
TP4  PT  [PTB]  (value not drawn)
TP5  PT  [PTB]  (value not drawn)
TP6  PT  [PTB]  (value not drawn)
U11  MX25R6435F  [SOP8L]
U12  LT1963EST-3.3  [SOT223_SC73]

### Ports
INTERNAL-SPI3_MISO, INTERNAL-SPI3_MOSI, INTERNAL-SPI3_SCK, INTERNAL-UART3_RX, INTERNAL-UART3_TX, ISM43362-BOOT0, ISM43362-DRDY_EXTI1, ISM43362-RST, ISM43362-SPI3_CSN, ISM43362-WAKEUP, QUADSPI_BK1_IO0, QUADSPI_BK1_IO1, QUADSPI_BK1_IO2, QUADSPI_BK1_IO3, QUADSPI_CLK, QUADSPI_NCS, SPBTLE-RF-IRQ_EXTI6, SPBTLE-RF-RST, SPBTLE-RF-SPI3_CSN, SPSGRF-915-GPIO3_EXTI5, SPSGRF-915-SDN, SPSGRF-915-SPI3_CSN

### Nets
3V3: C43.1 C45.1 C48.1 M1.5(Vin) M3.5(Vin) R26.2 U11.8(VCC)
3V3_WIFI: C44.1 C47.1 C50.1 C75.1 C76.1 M2.2(VDD) M2.14(VDD) M2.15(VBAT) R65.2 R66.2 U12.3(OUT)
5V: C49.1 U12.1(IN)
GND: C43.2 C44.2 C45.2 C47.2 C48.2 C49.2 C50.2 C75.2 C76.2 M1.6(GND) M2.1(GND) M2.3(GND) M2.17(GND) M2.20(GND) M2.35(GND) M2.36(GND) M2.37(GND) M2.38(GND) M2.39(GND) M2.40(GND) M2.41(GND) M2.42(GND) M2.43(GND) M2.44(GND) M3.6(GND) R64.2 TP6.1 U11.4(GND) U12.2(GND)
NetM1_4: M1.4(SPI_IRQ) ; port SPBTLE-RF-IRQ_EXTI6
NetM1_7: M1.7(SPI_SCLK) M2.11(ADC2/SCK) M3.7(SPI_CLK) ; port INTERNAL-SPI3_SCK
NetM1_8: M1.8(SPI_MISO) M2.10(ADC3/MISO) M3.8(SPI_MISO) ; port INTERNAL-SPI3_MISO
NetM1_9: M1.9(SPI_MOSI) M2.9(ADC4/MOSI) M3.9(SPI_MOSI) ; port INTERNAL-SPI3_MOSI
NetM1_10: M1.10(SPI_CS) ; port SPBTLE-RF-SPI3_CSN
NetM1_11: M1.11(BT_RESET) ; port SPBTLE-RF-RST
NetM2_4: M2.4(TMS) TP1.1
NetM2_5: M2.5(TCK) TP2.1
NetM2_6: M2.6(TDI) TP3.1
NetM2_7: M2.7(TDO) TP4.1
NetM2_8: M2.8(TRSTN) TP5.1
NetM2_12: M2.12(ADC1/SSN) R26.1 ; port ISM43362-SPI3_CSN
NetM2_13: M2.13(ADC0/DATARDY) ; port ISM43362-DRDY_EXTI1
NetM2_16: M2.16(WKUP) ; port ISM43362-WAKEUP
NetM2_21: M2.21(RX) ; port INTERNAL-UART3_TX
NetM2_22: M2.22(TX) ; port INTERNAL-UART3_RX
NetM2_28: M2.28(CFG0) R66.1
NetM2_29: M2.29(CFG1) R64.1 R65.1
NetM2_33: M2.33(BOOT0) ; port ISM43362-BOOT0
NetM2_34: M2.34(RSTN) ; port ISM43362-RST
NetM3_1: M3.1(GPIO_(3)) ; port SPSGRF-915-GPIO3_EXTI5
NetM3_10: M3.10(SPI_CS) ; port SPSGRF-915-SPI3_CSN
NetM3_11: M3.11(SDN) ; port SPSGRF-915-SDN
NetU1_41: U11.6(SCLK) ; port QUADSPI_CLK
NetU1_42: U11.1(CS#) ; port QUADSPI_NCS
NetU1_43: U11.5(SI/SIO0) ; port QUADSPI_BK1_IO0
NetU1_44: U11.2(SO/SIO1) ; port QUADSPI_BK1_IO1
NetU1_45: U11.3(WP#/SIO2) ; port QUADSPI_BK1_IO2
NetU1_46: U11.7(RESET#/SOI3) ; port QUADSPI_BK1_IO3

Not connected (* = marked no-connect by the designer): M1 1(EXT_LPCLK)* 2(GPIO2)* 3(ANA_TEST_0)*; M2 18(DP)* 19(DM)* 23(GPIO0)* 24(GPIO1)* 25(GPIO2)* 26(GPIO3)* 27(GPIO4)* 30(RES)* 31(RES)* 32(RES)*; M3 2(GPIO_(2))* 3(GPIO_(1))* 4(GPIO_(0))*

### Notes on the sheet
- (near C49) 0603
- (near C50) 0603
- Designed by DiZiC

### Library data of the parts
C43-C45 C47-C50 C75 C76 = CAP_NPOL: Capacitor_not polarized
M1 = SPBTLE-RF
M2 = ISM43362-M3G-L44: ISM43362-M3G-L44 Wifi Module 802.11 bgn
M3 = SPSGRF: SPSGRF-915or SPSGRF-868
R26 = RES: Resistor
R64-R66 = RES: Resistor; FITTED: NO
TP1-TP6 = PT: Point de test
U11 = MX25R6435F: MX25R6435F Serial Flash Memory 64M
U12 = LT1963EST-3.3: LT1963EST-3.3 LDO Low Noise 1.5A fast Transient Response

## Sheet MB1297_Peripherals.SchDoc: Peripherals
size A4; DocumentNumber: MB1297; Revision: D; SheetNumber: 10; SheetTotal: 11
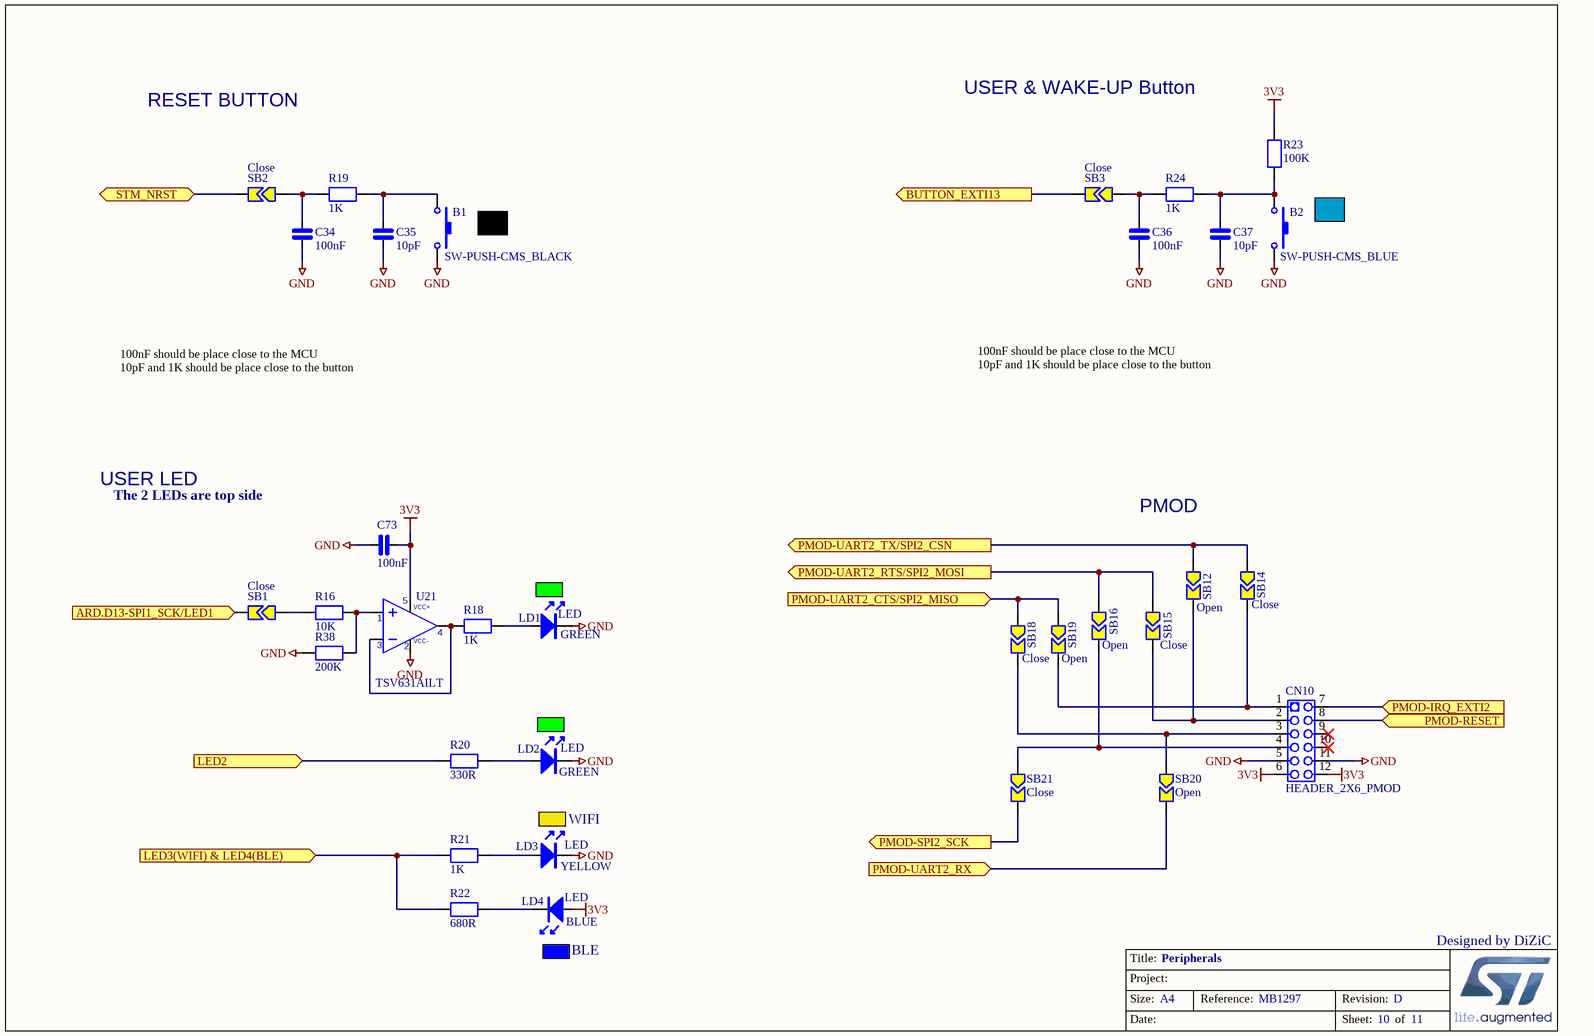
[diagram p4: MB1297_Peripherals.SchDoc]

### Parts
B1  SW-PUSH-CMS_BLACK  [SWI_WEALTHMETAL_TD-0341_4P - BACK]
B2  SW-PUSH-CMS_BLUE  [SWI_WEALTHMETAL_TD-0341_4P - BLUE]
C34  100nF  [0402_CAP_NPOL]
C35  10pF  [0402_CAP_NPOL]
C36  100nF  [0402_CAP_NPOL]
C37  10pF  [0402_CAP_NPOL]
C73  100nF  [0402_CAP_NPOL]
CN10  HEADER_2X6_PMOD  [Header F 2x6x2.54 TH H PMOD]
LD1  LED  Color: GREEN  [0603_LED_GREEN]
LD2  LED  Color: GREEN  [0603_LED_GREEN]
LD3  LED  Color: YELLOW  [0603_LED_Yellow]
LD4  LED  Color: BLUE  [0603_LED_Blue]
R16  10K  [0402_RES]
R18  1K  [0402_RES]
R19  1K  [0402_RES]
R20  330R  [0402_RES]
R21  1K  [0402_RES]
R22  680R  [0402_RES]
R23  100K  [0402_RES]
R24  1K  [0402_RES]
R38  200K  [0402_RES]
SB1  Close  [SB]
SB2  Close  [SB]
SB3  Close  [SB]
SB12  Open  [SB]
SB14  Close  [SB]
SB15  Close  [SB]
SB16  Open  [SB]
SB18  Close  [SB]
SB19  Open  [SB]
SB20  Open  [SB]
SB21  Close  [SB]
U21  TSV631AILT  [SOT23-5]

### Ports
ARD.D13-SPI1_SCK/LED1, BUTTON_EXTI13, LED2 (in), LED3(WIFI) & LED4(BLE), PMOD-IRQ_EXTI2, PMOD-RESET, PMOD-SPI2_SCK, PMOD-UART2_CTS/SPI2_MISO, PMOD-UART2_RTS/SPI2_MOSI, PMOD-UART2_RX, PMOD-UART2_TX/SPI2_CSN, STM_NRST

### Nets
3V3: C73.1 CN10.6 CN10.12 LD4.A R23.2 U21.5(V+)
GND: B1.2 B2.2 C34.2 C35.2 C36.2 C37.2 C73.2 CN10.5 CN10.11 LD1.K LD2.K LD3.K R38.1 U21.2(V-)
NetB1_1: B1.1 C35.1 R19.2
NetB2_1: B2.1 C37.1 R23.1 R24.2
NetC3_2: SB2.1 ; port STM_NRST
NetC34_1: C34.1 R19.1 SB2.2
NetC36_1: C36.1 R24.1 SB3.2
NetCN1_6: SB1.1 ; port ARD.D13-SPI1_SCK/LED1
NetCN10_1: CN10.1 SB14.1 SB19.1
NetCN10_2: CN10.2 SB12.1 SB15.1
NetCN10_3: CN10.3 SB18.1 SB20.2
NetCN10_4: CN10.4 SB16.1 SB21.2
NetCN10_7: CN10.7 ; port PMOD-IRQ_EXTI2
NetCN10_8: CN10.8 ; port PMOD-RESET
NetLD1_A: LD1.A R18.2
NetLD2_A: LD2.A R20.2
NetLD3_A: LD3.A R21.2
NetLD4_K: LD4.K R22.2
NetR16_1: R16.1 SB1.2
NetR16_2: R16.2 R38.2 U21.1(IN+)
NetR18_1: R18.1 U21.3(IN-) U21.4(OUT)
NetR20_1: R20.1 ; port LED2
NetR21_1: R21.1 R22.1 ; port LED3(WIFI) & LED4(BLE)
NetSB3_1: SB3.1 ; port BUTTON_EXTI13
NetSB12_2: SB12.2 SB14.2 ; port PMOD-UART2_TX/SPI2_CSN
NetSB15_2: SB15.2 SB16.2 ; port PMOD-UART2_RTS/SPI2_MOSI
NetSB18_2: SB18.2 SB19.2 ; port PMOD-UART2_CTS/SPI2_MISO
NetSB20_1: SB20.1 ; port PMOD-UART2_RX
NetSB21_1: SB21.1 ; port PMOD-SPI2_SCK

Not connected (* = marked no-connect by the designer): CN10 9* 10*

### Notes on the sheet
- RESET BUTTON
- USER & WAKE-UP Button
- 100nF should be place close to the MCU
  10pF and 1K should be place close to the button
- USER LED
- The 2 LEDs are top side
- PMOD
- (near LD3) WIFI
- (near LD4) BLE
- Designed by DiZiC

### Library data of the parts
B1 B2 = SW-PB_2: Push-button SMD; Order code RS: 102-412
C34-C37 C73 = CAP_NPOL: Capacitor_not polarized
CN10 = HEADER_2X6_PMOD: PMOD Connector Warning Specific Pinout
LD1-LD4 = LED: Light-Emitting Diode
R16 R18-R24 R38 = RES: Resistor
SB1-SB3 SB12 SB14-SB16 SB18-SB21 = Strap2: Solder Jumper; Solder: YES
U21 = TSV631AILT: TSV631AILT  Rail-to-rail input/output, 60 µA, 880 kHz, 5 V CMOS  operational amplifiers

## Sheet MB1297_NFC_SAFE.SchDoc: NFC & ST-SAFE Part
size A4; DocumentNumber: MB1297; Revision: D; SheetNumber: 7; SheetTotal: 11
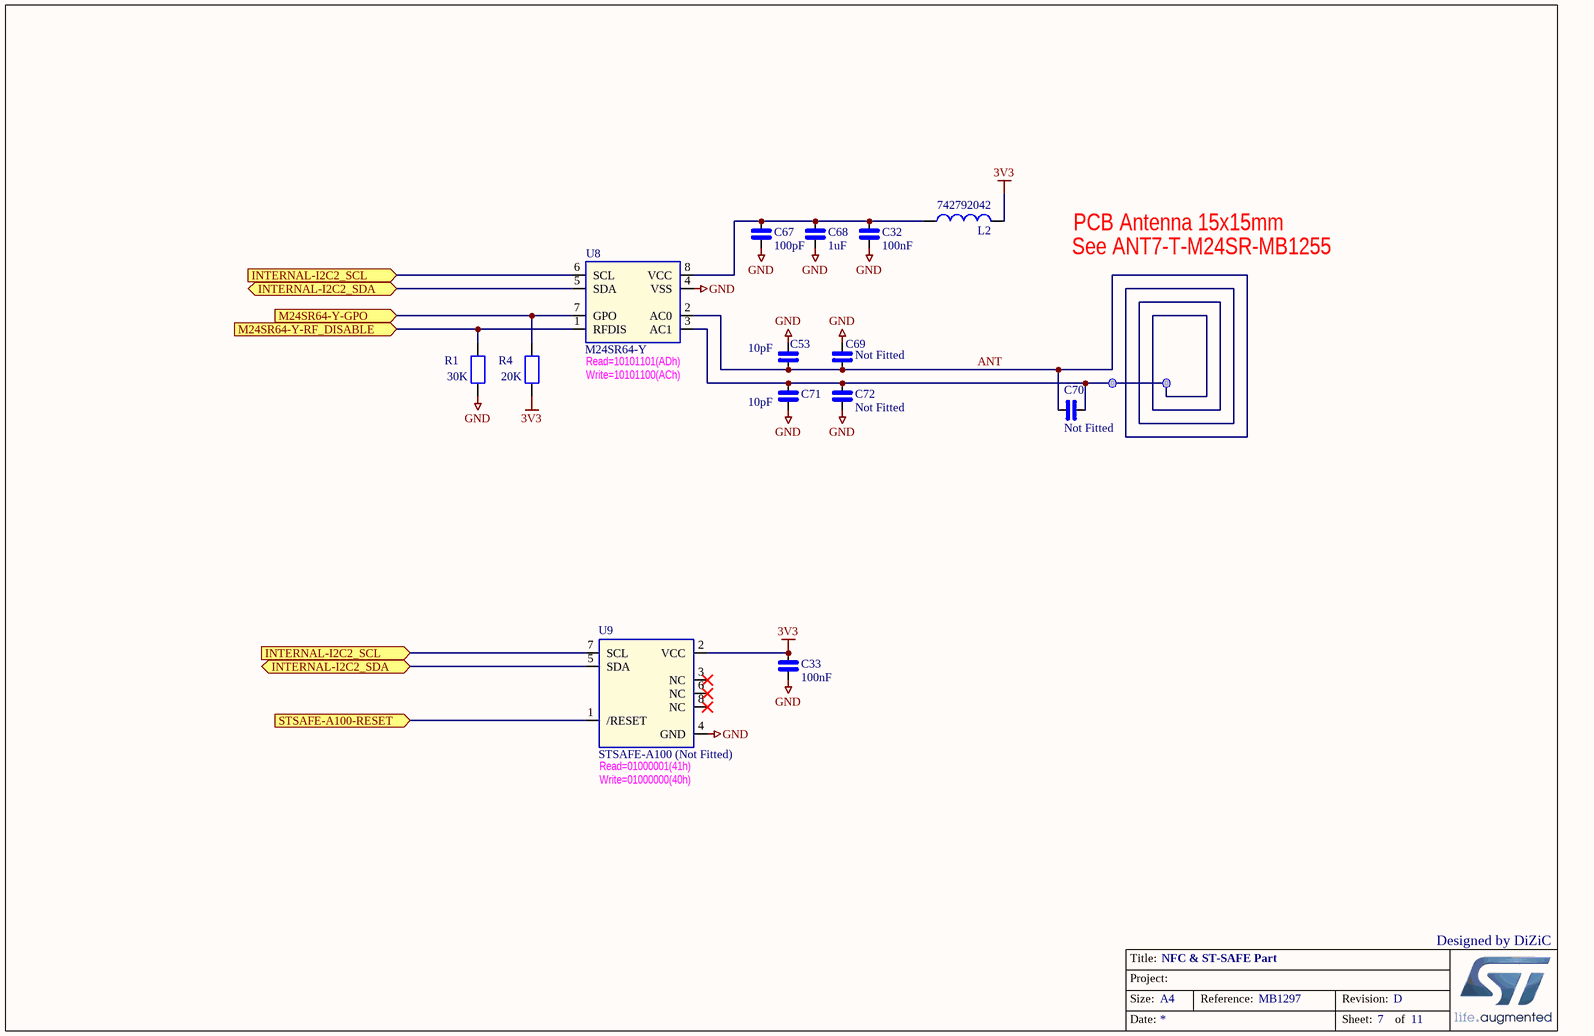
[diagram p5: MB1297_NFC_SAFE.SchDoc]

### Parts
C32  100nF  [0402_CAP_NPOL]
C33  100nF  [0402_CAP_NPOL]
C53  10pF  [0402_CAP_NPOL]
C67  100pF  [0402_CAP_NPOL]
C68  1uF  [0402_CAP_NPOL]
C69  Not Fitted  [0402_CAP_NPOL]
C70  Not Fitted  [0402_CAP_NPOL]
C71  10pF  [0402_CAP_NPOL]
C72  Not Fitted  [0402_CAP_NPOL]
L2  742792042  [0603L]
R1  30K  [0402_RES]
R4  20K  [0402_RES]
U8  M24SR64-Y  [SOP8]
U9  STSAFE-A100 (Not Fitted)  [SOP8]

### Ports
INTERNAL-I2C2_SCL, INTERNAL-I2C2_SDA, M24SR64-Y-GPO, M24SR64-Y-RF_DISABLE, STSAFE-A100-RESET

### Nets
3V3: C33.1 L2.2 R4.1 U9.2(VCC)
GND: C32.2 C33.2 C53.2 C67.2 C68.2 C69.2 C71.2 C72.2 R1.1 U8.4(VSS) U9.4(GND)
ANT: C53.1 C69.1 C70.1 C70.2 C71.1 C72.1 U8.2(AC0) U8.3(AC1)
NetC32_1: C32.1 C67.1 C68.1 L2.1 U8.8(VCC)
NetR1_2: R1.2 U8.1(RFDIS) ; port M24SR64-Y-RF_DISABLE
NetR4_2: R4.2 U8.7(GPO) ; port M24SR64-Y-GPO
NetR10_2: U8.6(SCL) U9.7(SCL) ; port INTERNAL-I2C2_SCL
NetR11_2: U8.5(SDA) U9.5(SDA) ; port INTERNAL-I2C2_SDA
NetU1_88: U9.1(/RESET) ; port STSAFE-A100-RESET

Not connected (* = marked no-connect by the designer): U9 3(NC)* 6(NC)* 8(NC)*

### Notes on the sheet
- PCB Antenna 15x15mm
- See ANT7-T-M24SR-MB1255
- (near U8) Read=10101101(ADh)
- Write=10101100(ACh)
- (near U9) Read=01000001(41h)
- (near U9) Write=01000000(40h)
- Designed by DiZiC

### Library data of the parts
C32 C33 C53 C67-C72 = CAP_NPOL: Capacitor_not polarized
L2 = Inductor: Value: 100uH
R1 R4 = RES: Resistor
U8 = M24SR64-Y: M24SR64-Y  64K_EEPROM NFC/RFID
U9 = STSAFE-A100

## Sheet MB1297_STLINK_V2-1.SCHDOC: ST-LINK/V2-1 with support of SWD only
size A4; DocumentNumber: MB1297; Revision: D; SheetNumber: 11; SheetTotal: 11
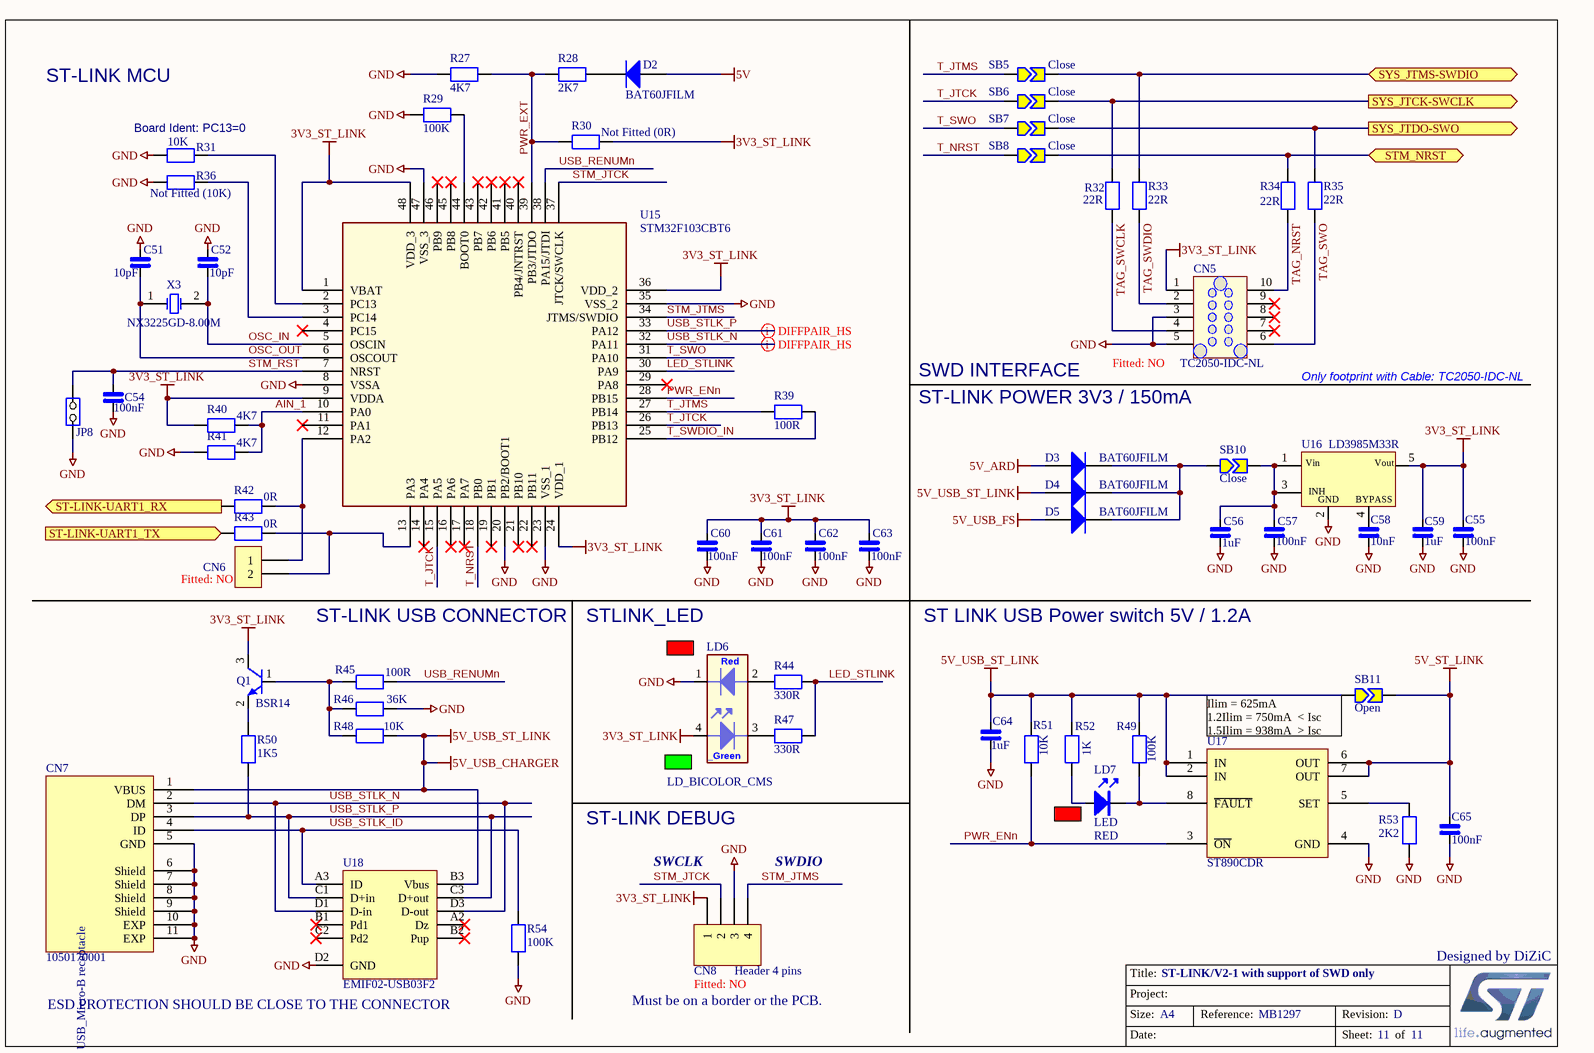
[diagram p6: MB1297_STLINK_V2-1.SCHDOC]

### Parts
C51  10pF  [0402_CAP_NPOL]
C52  10pF  [0402_CAP_NPOL]
C54  100nF  [0402_CAP_NPOL]
C55  100nF  [0402_CAP_NPOL]
C56  1uF  [0402_CAP_NPOL]
C57  100nF  [0402_CAP_NPOL]
C58  10nF  [0402_CAP_NPOL]
C59  1uF  [0402_CAP_NPOL]
C60  100nF  [0402_CAP_NPOL]
C61  100nF  [0402_CAP_NPOL]
C62  100nF  [0402_CAP_NPOL]
C63  100nF  [0402_CAP_NPOL]
C64  1uF  [0402_CAP_NPOL]
C65  100nF  [0402_CAP_NPOL]
CN5  TC2050-IDC-NL  Fitted: NO  [CON_TAG-C_TC2050-IDC-NL]
CN6  Fitted: NO  [CON_SAMTEC_TSW-102-07-G-S]  (hidden comment: header 2 pins 2.54mm)
CN7  1050170001  [CON_USBMICROB_MOLEX_105017-0001_H2P90]
CN8  Header 4 pins  Fitted: NO  [CON_SAMTEC_TSW-104-07-G-S]
D2  BAT60JFILM  [DIO_SOD323]
D3  BAT60JFILM  [DIO_SOD323]
D4  BAT60JFILM  [DIO_SOD323]
D5  BAT60JFILM  [DIO_SOD323]
JP8  Jumper_2.54mm  [CON_SAMTEC_TSW-102-07-G-S]  (value not drawn)
LD6  LD_BICOLOR_CMS  [LED_BI-GR_HSMF-A201-A00J1]
LD7  LED  Color: RED  [0603_LED_RED]
Q1  BSR14  [SOT23-3]
R27  4K7  [0402_RES]
R28  2K7  [0402_RES]
R29  100K  [0402_RES]
R30  Not Fitted (0R)  [0402_RES]
R31  10K  [0402_RES]
R32  22R  [0402_RES]
R33  22R  [0402_RES]
R34  22R  [0402_RES]
R35  22R  [0402_RES]
R36  Not Fitted (10K)  [0402_RES]
R39  100R  [0402_RES]
R40  4K7  [0402_RES]
R41  4K7  [0402_RES]
R42  0R  [0402_RES]
R43  0R  [0402_RES]
R44  330R  [0402_RES]
R45  100R  [0402_RES]
R46  36K  [0402_RES]
R47  330R  [0402_RES]
R48  10K  [0402_RES]
R49  100K  [0402_RES]
R50  1K5  [0402_RES]
R51  10K  [0402_RES]
R52  1K  [0402_RES]
R53  2K2  [0402_RES]
R54  100K  [0402_RES]
SB5  Close  [SB]
SB6  Close  [SB]
SB7  Close  [SB]
SB8  Close  [SB]
SB10  Close  [SB]
SB11  Open  [SB]
U15  STM32F103CBT6  [ICC_LQFP48_7X7_P050]
U16  LD3985M33R  [REG_SOT23-5L]
U17  ST890CDR  [ICC_SO8_5X4_P127]
U18  EMIF02-USB03F2  [ESD_FLIP-CHIP-BGA11_1P44X1P94_P050]
X3  NX3225GD-8.00M  [CRY_NX3225GD_2P]

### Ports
ST-LINK-UART1_RX, ST-LINK-UART1_TX, STM_NRST, SYS_JTCK-SWCLK, SYS_JTDO-SWO, SYS_JTMS-SWDIO

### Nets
3V3_ST_LINK: C55.1 C59.1 C60.1 C61.1 C62.1 C63.1 CN5.1 CN8.1 LD6.4 Q1.3(C) R30.1 R40.2 U15.1(VBAT) U15.9(VDDA) U15.24(VDD_1) U15.36(VDD_2) U15.48(VDD_3) U16.5(Vout)
5V: D2.1(A)
5V_ARD: D3.1(A)
5V_ST_LINK: C65.1 SB11.1 U17.6(OUT) U17.7(OUT)
5V_USB_CHARGER: C64.1 CN7.1(VBUS) D4.1(A) R48.1 R49.2 R51.2 R52.2 SB11.2 U17.1(IN) U17.2(IN) U18.B3(Vbus)  [also labelled 5V_USB_ST_LINK]
5V_USB_FS: D5.1(A)
GND: C51.1 C52.1 C54.2 C55.2 C56.2 C57.2 C58.2 C59.2 C60.2 C61.2 C62.2 C63.2 C64.2 C65.2 CN5.3 CN5.5 CN7.5(GND) CN7.6(Shield) CN7.7(Shield) CN7.8(Shield) CN7.9(Shield) CN7.10(EXP) CN7.11(EXP) CN8.3 JP8.1(COMMON) LD6.1 R27.2 R29.2 R31.2 R36.2 R41.2 R46.1 R53.1 R54.2 U15.8(VSSA) U15.20(PB2/BOOT1) U15.23(VSS_1) U15.35(VSS_2) U15.47(VSS_3) U16.2(GND) U17.4(GND) U18.D2(GND)
AIN_1: R40.1 R41.1 U15.10(PA0)
LED_STLINK: R44.1 R47.1 U15.30(PA9)
OSC_IN: C52.2 U15.5(OSCIN) X3.2(OSC2)
OSC_OUT: C51.2 U15.6(OSCOUT) X3.1(OSC1)
PWR_ENn: R51.1 U15.28(PB15) U17.3(~{ON})
PWR_EXT: R27.1 R28.2 R30.2 U15.39(PB3/JTDO)
STM_JTCK: CN8.2 U15.37(JTCK/SWCLK)
STM_JTMS: CN8.4 U15.34(JTMS/SWDIO)
STM_RST: C54.1 JP8.2(NO) U15.7(NRST)
T_JTCK: SB6.2 U15.15(PA5) U15.26(PB13)
T_JTMS: R39.2 SB5.2 U15.27(PB14)
T_NRST: SB8.2 U15.18(PB0)
T_SWDIO_IN: R39.1 U15.25(PB12)
T_SWO: SB7.2 U15.31(PA10)
TAG_NRST: CN5.10 R34.1
TAG_SWCLK: CN5.4 R32.1
TAG_SWDIO: CN5.2 R33.1
TAG_SWO: CN5.6 R35.1
USB_RENUMn: R45.1 U15.38(PA15/JTDI)
USB_STLK_ID: CN7.4(ID) R54.1 U18.A3(ID)
USB_STLK_N: CN7.2(DM) U15.32(PA11) U18.D1(D-in) U18.D3(D-out)
USB_STLK_P: CN7.3(DP) R50.2 U15.33(PA12) U18.C1(D+in) U18.C3(D+out)
NetC3_2: R34.2 SB8.1 ; port STM_NRST
NetC56_1: C56.1 C57.1 SB10.1 U16.1(Vin) U16.3(CE)
NetC58_1: C58.1 U16.4(BYPASS)
NetCN6_1: CN6.1 R42.1 U15.12(PA2)
NetCN6_2: CN6.2 R43.1 U15.13(PA3)
NetD2_2: D2.2(K) R28.1
NetD3_2: D3.2(K) D4.2(K) D5.2(K) SB10.2
NetLD6_2: LD6.2 R44.2
NetLD6_3: LD6.3 R47.2
NetLD7_A: LD7.A R52.1
NetLD7_K: LD7.K R49.1 U17.8(~{FAULT})
NetQ1_1: Q1.1(B) R45.2 R46.2 R48.2
NetQ1_2: Q1.2(E) R50.1
NetR29_1: R29.1 U15.44(BOOT0)
NetR31_1: R31.1 U15.2(PC13)
NetR32_2: R32.2 SB6.1 ; port SYS_JTCK-SWCLK
NetR33_2: R33.2 SB5.1 ; port SYS_JTMS-SWDIO
NetR35_2: R35.2 SB7.1 ; port SYS_JTDO-SWO
NetR36_1: R36.1 U15.3(PC14)
NetR42_2: R42.2 ; port ST-LINK-UART1_RX
NetR43_2: R43.2 ; port ST-LINK-UART1_TX
NetR53_2: R53.2 U17.5(SET)

Not connected (* = marked no-connect by the designer): CN5 7* 8* 9*; U15 4(PC15)* 11(PA1)* 14(PA4)* 16(PA6)* 17(PA7)* 19(PB1)* 21(PB10)* 22(PB11)* 29(PA8)* 40(PB4/JNTRST)* 41(PB5)* 42(PB6)* 43(PB7)* 45(PB8)* 46(PB9)*; U18 A2(Dz)* B1(Pd1)* B2(Pup)* C2(Pd2)*

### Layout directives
differential pair: USB_STLK_N, USB_STLK_P

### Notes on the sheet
- ST-LINK MCU
- (near R31) Board Ident: PC13=0
- SWD INTERFACE
- Only footprint with Cable: TC2050-IDC-NL
- ST-LINK POWER 3V3 / 150mA
- ST-LINK USB CONNECTOR
- STLINK_LED
- ST LINK USB Power switch 5V / 1.2A
- (near SB11) Ilim = 625mA
  1.2Ilim = 750mA  < Isc
  1.5Ilim = 938mA  > Isc
- ST-LINK DEBUG
- SWCLK
- SWDIO
- Must be on a border or the PCB.
- Designed by DiZiC
- (near U18) ESD PROTECTION SHOULD BE CLOSE TO THE CONNECTOR

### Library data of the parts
C51 C52 C54-C65 = CAP_NPOL: Capacitor_not polarized
CN5 = Tag-10-C: Tag_Connector Header, 10-Pin, Dual row No legs; Manuf_Part_1: TC2050-IDC-NL-FP; Ordered_By: Subcon
CN6 = Header 2 pins: Manuf_1: SAMTEC; Manuf_Part_2: 4711955140470; Manuf_2: KONTEC; Manuf_Part_1: TSW-102-07-x-S; Order_Code: 423-2841; Ordered_By: Subcon
CN7 = 1050170001: USB-MICRO-B, 1050170001, SMT, MOLEX; Fitted: YES; Ordered_By: Subcon
CN8 = Header 4: Header, 4-Pin; Manuf_1: Samtec; Manuf_Part_1: TSW-104-07-x-S; Ordered_By: Subcon
D2-D5 = BAT60JFILM: Manuf_1: STM; ECCN_US/EU: EAR99/NEC; Ref St: 9151097; Fitted: YES
JP8 = TSW-102-07-x-S: Connector jumper 1 position; Manuf_1: SAMTEC; Manuf_Part_2: 4711955140470; Manuf_2: KONTEC; Order_Code: 423-2841; Fitted: YES; Ordered_By: Subcon
LD6 = LD_BICOLOR_CMS: Bicolor Led; Manuf_Part_1: HSMF-A201-A00J1; Manuf_1: Avago Technologies; Manuf_2: everluck; Manuf_Part_2: LE-RGW35280; ECCN_US/EU: EAR99/NEC; Fitted: YES; Ordered_By: Subcon
LD7 = LED: Light-Emitting Diode
Q1 = BSR14: BSR14 NPN switching transistor SOT23 (Marking U8)
R27-R29 R31-R35 R39-R54 = RES: Resistor
R30 R36 = RES: Resistor; FITTED: NO
SB5-SB8 SB10 SB11 = Strap2: Solder Jumper; Solder: YES
U15 = STM32F103CBT6: Medium-density performance line ARM-based 32-bit MCU with 128KB Flash; Manuf_1: STM; ECCN_US/EU: 3A991A2/NEC; Fitted: YES
U16 = LD3985M33R: Ultra low drop-low noise BiCMOS voltage, regulators low ESR capacitors compatible; Manuf_1: STM; Ref St: 9176161; ECCN_US/EU: EAR99/NEC; Fitted: YES
U17 = ST890CDR: 1.2 A current limited high-side power switch with thermal shutdown; Manuf_1: STM; ECCN_US/EU: EAR99/NEC; Fitted: YES
U18 = EMIF02-USB03F2: 2-line IPAD, EMI filter including ESD protection; Manuf_1: STM; ECCN_US/EU: EAR99/NEC; Fitted: YES; REF_STM: 9179037
X3 = XTAL_8M_NX3225GD: Crystal 8Mhz, 8pF, -+50PPM, SMD; Manuf_1: NDK; Manuf_Part_1: NX3225GD 8MHz EXS00A-CG04874; ECCN_US/EU: EAR99/NEC; NDK Ref: X3127326; Ref St: 9157029; Fitted: YES; Ordered_By: STM

## Sheet MB1297_Arduino.SchDoc: Arduino Uno connector
size A4; DocumentNumber: MB1297; Revision: D; SheetNumber: 9; SheetTotal: 11
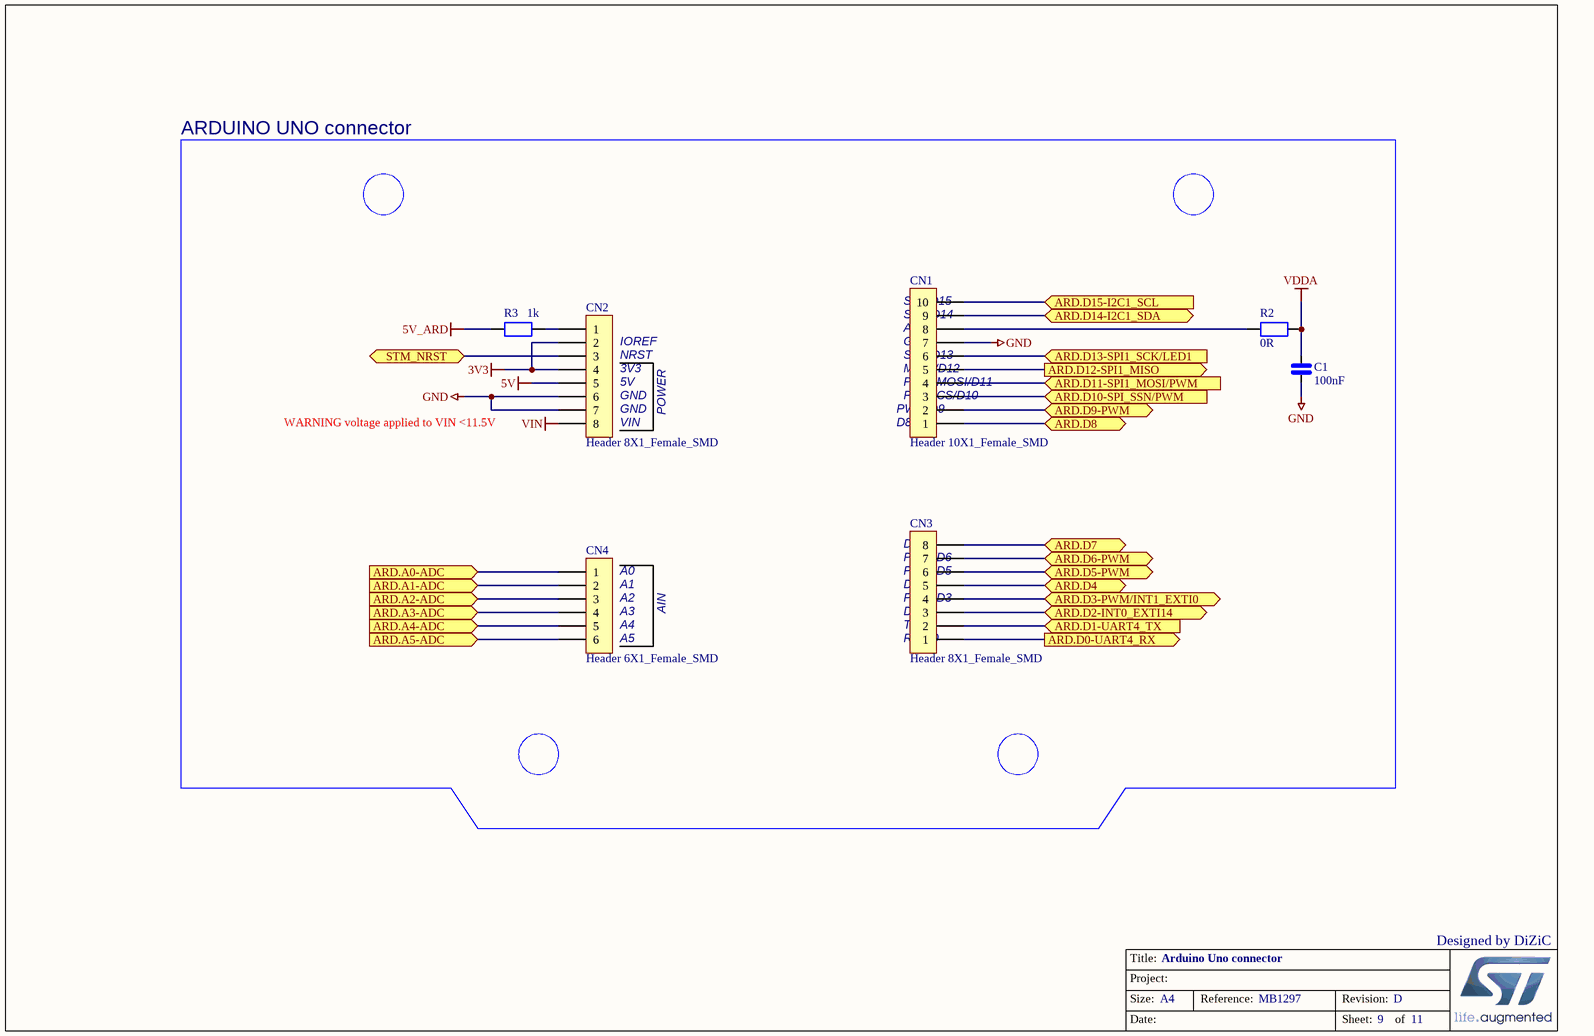
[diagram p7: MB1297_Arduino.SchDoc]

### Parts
C1  100nF  [0402_CAP_NPOL]
CN1  Header 10X1_Female_SMD  [F-V50XC-1X10R-LF]
CN2  Header 8X1_Female_SMD  [F-V50XC-1X08R-LF]
CN3  Header 8X1_Female_SMD  [F-V50XC-1X08R-LF]
CN4  Header 6X1_Female_SMD  [F-V50XC-1X06R-LF]
R2  0R  [0402_RES]
R3  1k  [0402_RES]

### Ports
ARD.A0-ADC, ARD.A1-ADC, ARD.A2-ADC, ARD.A3-ADC, ARD.A4-ADC, ARD.A5-ADC, ARD.D0-UART4_RX, ARD.D1-UART4_TX, ARD.D2-INT0_EXTI14, ARD.D3-PWM/INT1_EXTI0, ARD.D4, ARD.D5-PWM, ARD.D6-PWM, ARD.D7, ARD.D8, ARD.D9-PWM, ARD.D10-SPI_SSN/PWM, ARD.D11-SPI1_MOSI/PWM, ARD.D12-SPI1_MISO, ARD.D13-SPI1_SCK/LED1, ARD.D14-I2C1_SDA, ARD.D15-I2C1_SCL, STM_NRST

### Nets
3V3: CN2.2 CN2.4
5V: CN2.5
5V_ARD: R3.1
GND: C1.2 CN1.7 CN2.6 CN2.7
VDDA: C1.1 R2.2
VIN: CN2.8
NetC3_2: CN2.3 ; port STM_NRST
NetCN1_1: CN1.1 ; port ARD.D8
NetCN1_2: CN1.2 ; port ARD.D9-PWM
NetCN1_3: CN1.3 ; port ARD.D10-SPI_SSN/PWM
NetCN1_4: CN1.4 ; port ARD.D11-SPI1_MOSI/PWM
NetCN1_5: CN1.5 ; port ARD.D12-SPI1_MISO
NetCN1_6: CN1.6 ; port ARD.D13-SPI1_SCK/LED1
NetCN1_8: CN1.8 R2.1
NetCN1_9: CN1.9 ; port ARD.D14-I2C1_SDA
NetCN1_10: CN1.10 ; port ARD.D15-I2C1_SCL
NetCN2_1: CN2.1 R3.2
NetCN3_1: CN3.1 ; port ARD.D0-UART4_RX
NetCN3_2: CN3.2 ; port ARD.D1-UART4_TX
NetCN3_3: CN3.3 ; port ARD.D2-INT0_EXTI14
NetCN3_4: CN3.4 ; port ARD.D3-PWM/INT1_EXTI0
NetCN3_5: CN3.5 ; port ARD.D4
NetCN3_6: CN3.6 ; port ARD.D5-PWM
NetCN3_7: CN3.7 ; port ARD.D6-PWM
NetCN3_8: CN3.8 ; port ARD.D7
NetCN4_1: CN4.1 ; port ARD.A0-ADC
NetCN4_2: CN4.2 ; port ARD.A1-ADC
NetCN4_3: CN4.3 ; port ARD.A2-ADC
NetCN4_4: CN4.4 ; port ARD.A3-ADC
NetCN4_5: CN4.5 ; port ARD.A4-ADC
NetCN4_6: CN4.6 ; port ARD.A5-ADC

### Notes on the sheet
- ARDUINO UNO connector
- (near CN1) SCL/D15
- (near CN2) IOREF
- (near CN2) NRST
- (near CN2) 3V3
- (near CN2) 5V
- (near CN1) SDA/D14
- (near CN1) SCK/D13
- (near CN1) MISO/D12
- (near CN1) PWM/MOSI/D11
- (near CN1) AVDD
- (near CN1) GND
- WARNING voltage applied to VIN <11.5V
- (near CN2) GND
- (near CN2) VIN
- POWER
- (near CN1) D8
- (near CN1) PWM/D9
- (near CN1) PWM/CS/D10
- (near CN4) A0
- (near CN3) PWM/D5
- (near CN3) PWM/D6
- (near CN3) D7
- (near CN4) A1
- (near CN4) A2
- (near CN4) A3
- (near CN4) A4
- (near CN4) A5
- AIN
- (near CN3) RX/D0
- (near CN3) TX/D1
- (near CN3) D2
- (near CN3) D4
- (near CN3) PWM/D3
- Designed by DiZiC

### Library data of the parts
C1 = CAP_NPOL: Capacitor_not polarized
CN1 = Header 10X1_Female_SMD: Header, 10-Pin, SMD, Single row,female
CN2 CN3 = Header 8X1_Female_SMD: Header, 8-Pin, SMD, Single row,female
CN4 = Header 6X1_Female_SMD: Header, 6-Pin, SMD, Single row,female
R2 R3 = RES: Resistor

## Sheet MB1297_MEMS.SchDoc: MEMS Sensors
size A4; DocumentNumber: MB1297; Revision: D; SheetNumber: 6; SheetTotal: 11
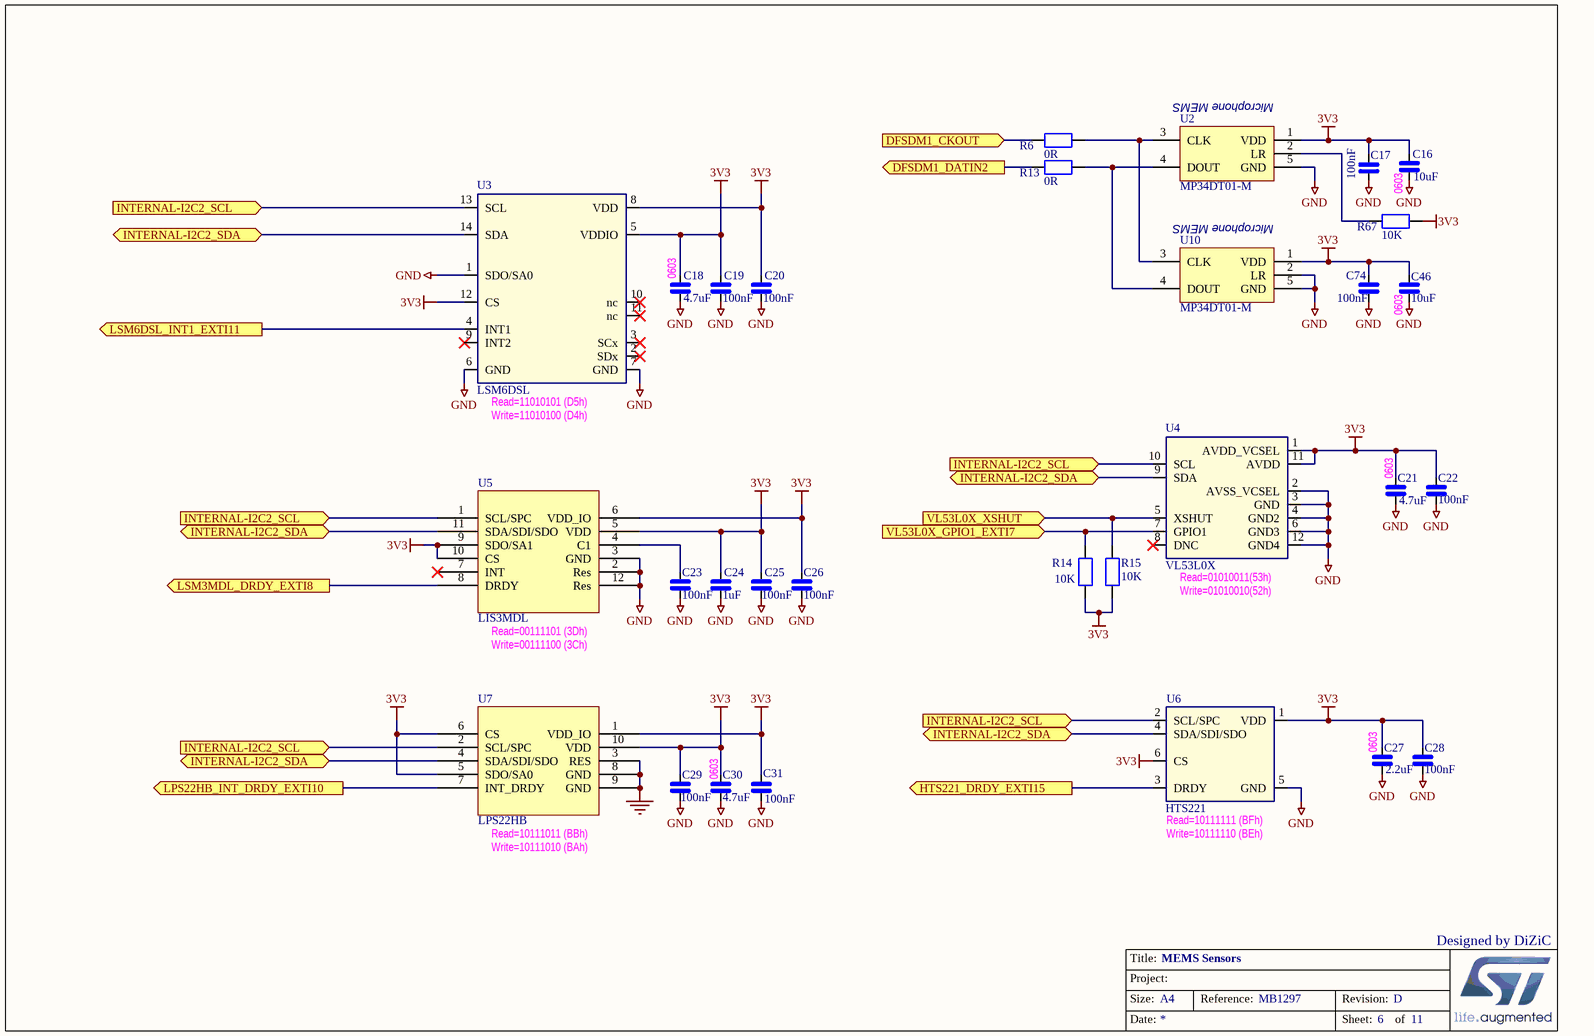
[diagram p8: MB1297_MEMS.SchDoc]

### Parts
C16  10uF  [0603_CAP_NPOL]
C17  100nF  [0402_CAP_NPOL]
C18  4.7uF  [0603_CAP_NPOL]
C19  100nF  [0402_CAP_NPOL]
C20  100nF  [0402_CAP_NPOL]
C21  4.7uF  [0603_CAP_NPOL]
C22  100nF  [0402_CAP_NPOL]
C23  100nF  [0402_CAP_NPOL]
C24  1uF  [0402_CAP_NPOL]
C25  100nF  [0402_CAP_NPOL]
C26  100nF  [0402_CAP_NPOL]
C27  2.2uF  [0603_CAP_NPOL]
C28  100nF  [0402_CAP_NPOL]
C29  100nF  [0402_CAP_NPOL]
C30  4.7uF  [0603_CAP_NPOL]
C31  100nF  [0402_CAP_NPOL]
C46  10uF  [0603_CAP_NPOL]
C74  100nF  [0402_CAP_NPOL]
R6  0R  [0402_RES]
R13  0R  [0402_RES]
R14  10K  [0402_RES]
R15  10K  [0402_RES]
R67  10K  [0402_RES]
U2  MP34DT01-M  [HCLGA-4LD 3x4x1]
U3  LSM6DSL  [LGA14L-2.5X3X0.86p0.5]
U4  VL53L0X  [LGA12-optical]
U5  LIS3MDL  [VFLGA12-2x2x1]
U6  HTS221  [HLGA6L-2x2x0.9]
U7  LPS22HB  [HLGA10L-2X2X0.76]
U10  MP34DT01-M  [HCLGA-4LD 3x4x1]

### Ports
DFSDM1_CKOUT, DFSDM1_DATIN2, HTS221_DRDY_EXTI15, INTERNAL-I2C2_SCL, INTERNAL-I2C2_SDA, LPS22HB_INT_DRDY_EXTI10, LSM3MDL_DRDY_EXTI8, LSM6DSL_INT1_EXTI11, VL53L0X_GPIO1_EXTI7, VL53L0X_XSHUT

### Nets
3V3: C16.1 C17.2 C18.1 C19.1 C20.1 C21.1 C22.1 C24.1 C25.1 C26.1 C27.1 C28.1 C29.1 C30.1 C31.1 C46.1 C74.1 R14.1 R15.1 R67.1 U2.1(VDD) U3.5(VDDIO) U3.8(VDD) U3.12(CS) U4.1(AVDD_VCSEL) U4.11(AVDD) U5.5(VDD) U5.6(VDD_IO) U5.9(SDO/SA1) U5.10(CS) U6.1(VDD) U6.6(CS) U7.1(VDD_IO) U7.5(SDO/SA0) U7.6(CS) U7.10(VDD) U10.1(VDD)
GND: C16.2 C17.1 C18.2 C19.2 C20.2 C21.2 C22.2 C23.2 C24.2 C25.2 C26.2 C27.2 C28.2 C29.2 C30.2 C31.2 C46.2 C74.2 U2.5(GND) U3.1(SDO/SA0) U3.6(GND) U3.7(GND) U4.2(AVSS_VCSEL) U4.3(GND) U4.4(GND2) U4.6(GND3) U4.12(GND4) U5.2(Res) U5.3(GND) U5.12(Res) U6.5(GND) U7.3(RES) U7.8(GND) U7.9(GND) U10.2(LR) U10.5(GND)
NetC23_1: C23.1 U5.4(C1)
NetR6_1: R6.1 U2.3(CLK) U10.3(CLK)
NetR6_2: R6.2 ; port DFSDM1_CKOUT
NetR10_2: U3.13(SCL) U4.10(SCL) U5.1(SCL/SPC) U6.2(SCL/SPC) U7.2(SCL/SPC) ; port INTERNAL-I2C2_SCL
NetR11_2: U3.14(SDA) U4.9(SDA) U5.11(SDA/SDI/SDO) U6.4(SDA/SDI/SDO) U7.4(SDA/SDI/SDO) ; port INTERNAL-I2C2_SDA
NetR13_1: R13.1 U2.4(DOUT) U10.4(DOUT)
NetR13_2: R13.2 ; port DFSDM1_DATIN2
NetR14_2: R14.2 U4.7(GPIO1) ; port VL53L0X_GPIO1_EXTI7
NetR15_2: R15.2 U4.5(XSHUT) ; port VL53L0X_XSHUT
NetR67_2: R67.2 U2.2(LR)
NetU1_57: U7.7(INT_DRDY) ; port LPS22HB_INT_DRDY_EXTI10
NetU1_58: U3.4(INT1) ; port LSM6DSL_INT1_EXTI11
NetU1_62: U6.3(DRDY) ; port HTS221_DRDY_EXTI15
NetU1_65: U5.8(DRDY) ; port LSM3MDL_DRDY_EXTI8

Not connected (* = marked no-connect by the designer): U3 2(SDx)* 3(SCx)* 9(INT2)* 10(nc)* 11(nc)*; U4 8(DNC)*; U5 7(INT)*

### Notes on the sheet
- (near U2) Microphone MEMS
- (near U10) Microphone MEMS
- (near C16) 0603
- (near C18) 0603
- (near C46) 0603
- (near U3) Read=11010101 (D5h)
- (near U3) Write=11010100 (D4h)
- (near C21) 0603
- (near U4) Read=01010011(53h)
- (near U5) Read=00111101 (3Dh)
- Write=00111100 (3Ch)
- (near U4) Write=01010010(52h)
- (near C30) 0603
- (near C27) 0603
- (near U7) Read=10111011 (BBh)
- Write=10111010 (BAh)
- (near U6) Read=10111111 (BFh)
- (near U6) Write=10111110 (BEh)
- Designed by DiZiC

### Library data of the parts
C16-C31 C46 C74 = CAP_NPOL: Capacitor_not polarized
R6 R13-R15 R67 = RES: Resistor
U2 U10 = MP34DT01: MEMS audio microphone
U3 = LSM6DSL: Accelero + Gyro MEMS (6 Axis)
U4 = VL53L0X: Proximity sensor MEMS
U5 = LIS3MDL: IC,Sensor; Provider: MMCC; Vendor: ST
U6 = HTS221: Humidity + Temp MEMS
U7 = LPS22HB: IC,Sensor; Provider: MMCC; Vendor: ST

## Sheet MB1297_USB_OTG_FS.SchDoc: USB_OTG_FS
size A4; DocumentNumber: MB1297; Revision: D; SheetNumber: 4; SheetTotal: 11
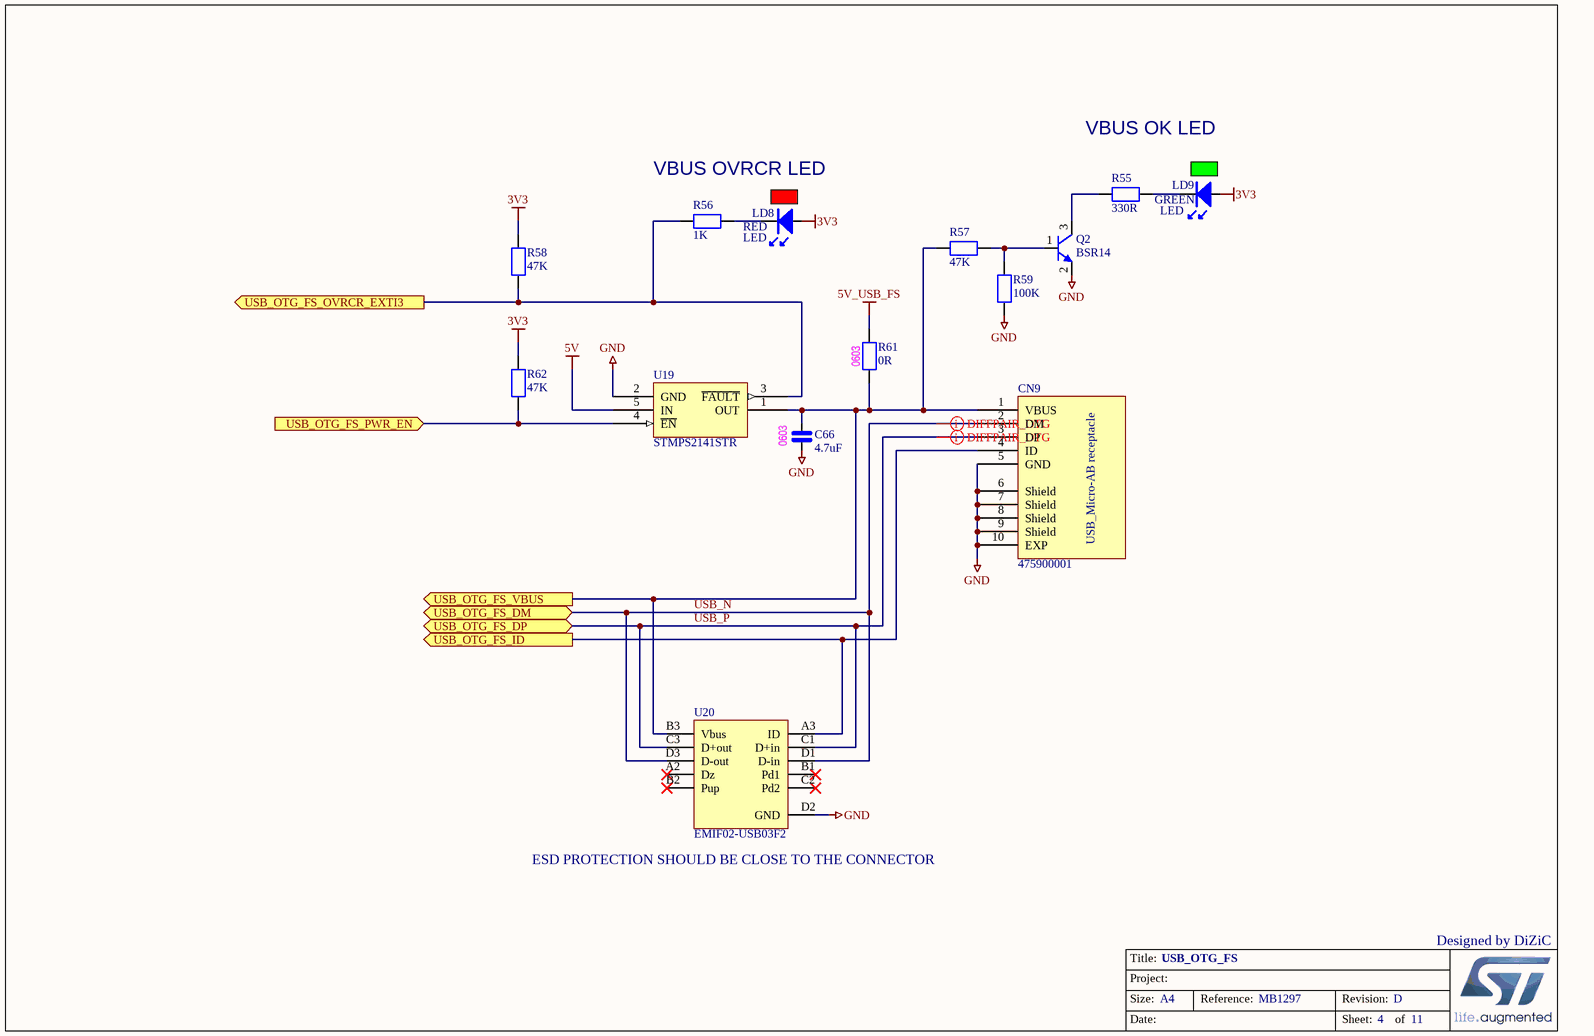
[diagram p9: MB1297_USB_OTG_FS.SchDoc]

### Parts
C66  4.7uF  [0603_CAP_NPOL]
CN9  475900001  [CON_USBMICROAB_MOLEX_47590-0001_H3]
LD8  LED  Color: RED  [0603_LED_RED]
LD9  LED  Color: GREEN  [0603_LED_GREEN]
Q2  BSR14  [SOT23-3]
R55  330R  [0402_RES]
R56  1K  [0402_RES]
R57  47K  [0402_RES]
R58  47K  [0402_RES]
R59  100K  [0402_RES]
R61  0R  [0603_RES]
R62  47K  [0402_RES]
U19  STMPS2141STR  [MOS_SOT23-5L]
U20  EMIF02-USB03F2  [ESD_FLIP-CHIP-BGA11_1P44X1P94_P050]

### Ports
USB_OTG_FS_DM (bidir), USB_OTG_FS_DP (bidir), USB_OTG_FS_ID (out), USB_OTG_FS_OVRCR_EXTI3 (out), USB_OTG_FS_PWR_EN (in), USB_OTG_FS_VBUS (out)

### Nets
3V3: LD8.A LD9.A R58.1 R62.1
5V: U19.5(IN)
5V_USB_FS: R61.1
GND: C66.2 CN9.5(GND) CN9.6(Shield) CN9.7(Shield) CN9.8(Shield) CN9.9(Shield) CN9.10(EXP) Q2.2(E) R59.1 U19.2(GND) U20.D2(GND)
USB_N: CN9.2(DM) U20.D1(D-in) U20.D3(D-out) ; port USB_OTG_FS_DM
USB_P: CN9.3(DP) U20.C1(D+in) U20.C3(D+out) ; port USB_OTG_FS_DP
NetC66_1: C66.1 CN9.1(VBUS) R57.1 R61.2 U19.1(OUT) U20.B3(Vbus) ; port USB_OTG_FS_VBUS
NetCN9_4: CN9.4(ID) U20.A3(ID) ; port USB_OTG_FS_ID
NetLD8_K: LD8.K R56.2
NetLD9_K: LD9.K R55.2
NetQ2_1: Q2.1(B) R57.2 R59.2
NetQ2_3: Q2.3(C) R55.1
NetR56_1: R56.1 R58.2 U19.3(~{FAULT}) ; port USB_OTG_FS_OVRCR_EXTI3
NetR62_2: R62.2 U19.4(~{EN}) ; port USB_OTG_FS_PWR_EN

Not connected (* = marked no-connect by the designer): U20 A2(Dz)* B1(Pd1)* B2(Pup)* C2(Pd2)*

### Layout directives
differential pair: USB_N, USB_P

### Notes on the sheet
- VBUS OVRCR LED
- VBUS OK LED
- (near R61) 0603
- (near C66) 0603
- (near U20) ESD PROTECTION SHOULD BE CLOSE TO THE CONNECTOR
- Designed by DiZiC

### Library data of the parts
C66 = CAP_NPOL: Capacitor_not polarized
CN9 = 475900001: USB-MICRO-AB, 47590-0001, SMT, MOLEX; Fitted: YES; Ordered_By: Subcon
LD8 LD9 = LED: Light-Emitting Diode
Q2 = BSR14: as Q1 on sheet MB1297_STLINK_V2-1
R55-R59 R61 R62 = RES: Resistor
U19 = STMPS2141STR: Enhanced single channel power switches; Manuf_1: STM; ECCN_US/EU: EAR99/NEC; Ref St: 9159003; Fitted: YES
U20 = EMIF02-USB03F2: as U18 on sheet MB1297_STLINK_V2-1

## Sheet MB1297_POWER.SchDoc: POWER SUPPLY
size A4; DocumentNumber: MB1297; Revision: D; SheetNumber: 8; SheetTotal: 11
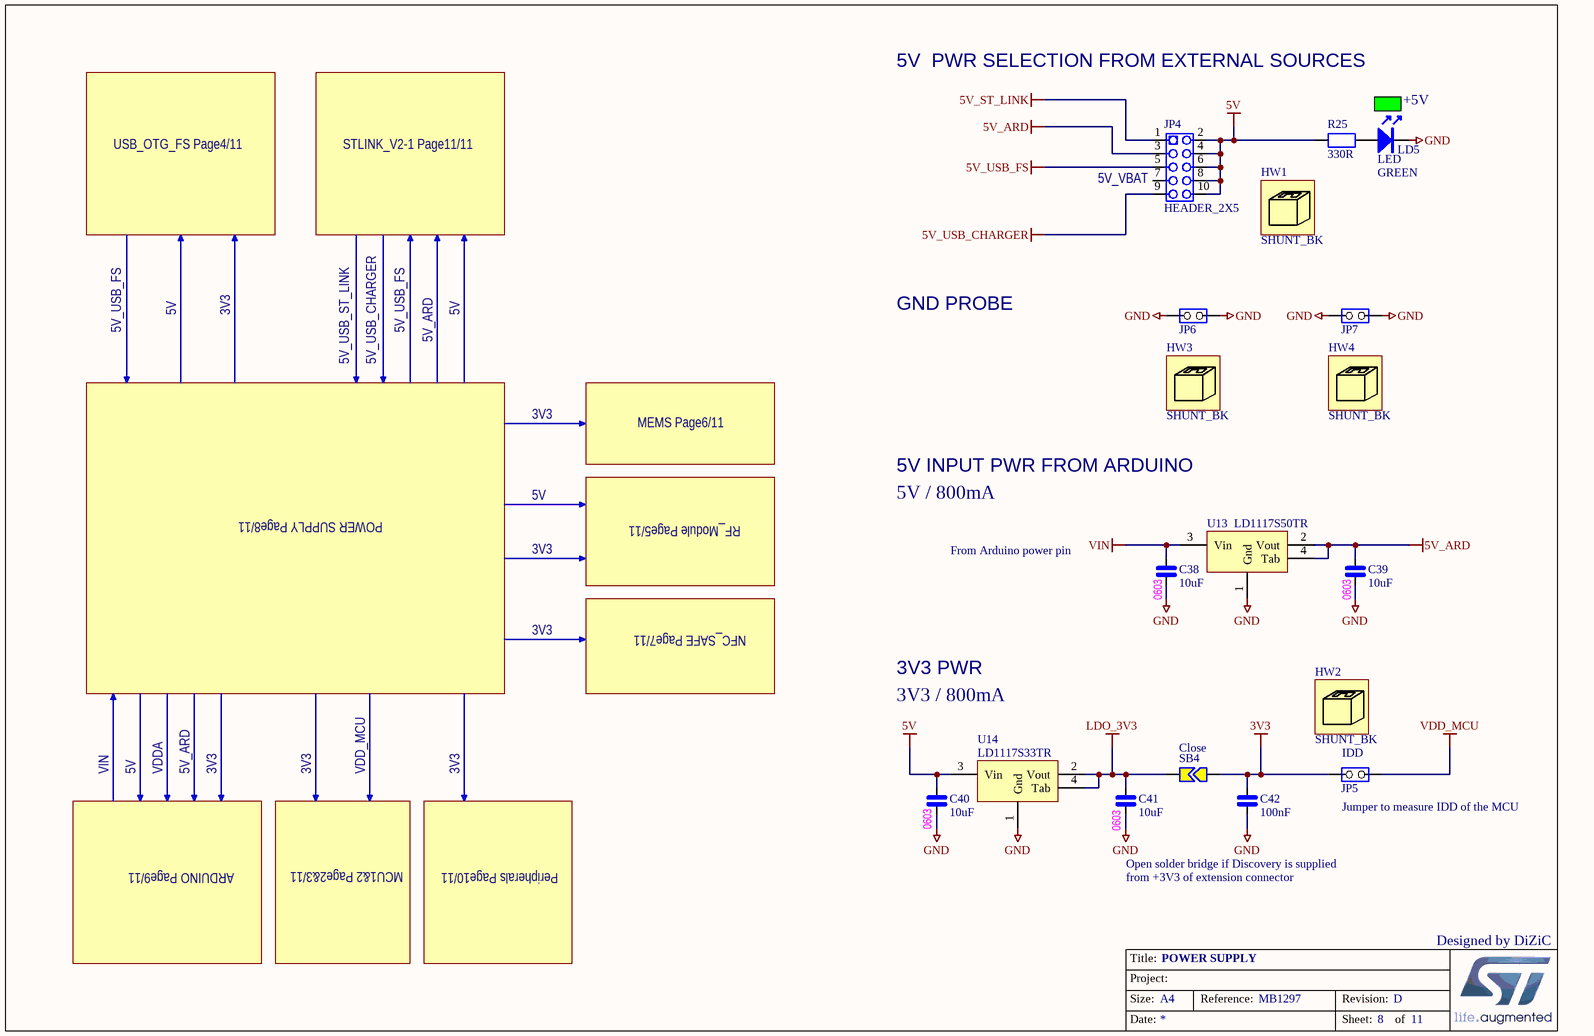
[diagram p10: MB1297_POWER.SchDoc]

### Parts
C38  10uF  [0603_CAP_NPOL]
C39  10uF  [0603_CAP_NPOL]
C40  10uF  [0603_CAP_NPOL]
C41  10uF  [0603_CAP_NPOL]
C42  100nF  [0402_CAP_NPOL]
HW1  SHUNT_BK  (mechanical)
HW2  SHUNT_BK  (mechanical)
HW3  SHUNT_BK  (mechanical)
HW4  SHUNT_BK  (mechanical)
JP4  HEADER_2X5  [Header M 2x5x2.54 TH V]
JP5  Jumper_2.54mm  [CON_SAMTEC_TSW-102-07-G-S]  (value not drawn)
JP6  Jumper_2.54mm  [CON_SAMTEC_TSW-102-07-G-S]  (value not drawn)
JP7  Jumper_2.54mm  [CON_SAMTEC_TSW-102-07-G-S]  (value not drawn)
LD5  LED  Color: GREEN  [0603_LED_GREEN]
R25  330R  [0402_RES]
SB4  Close  [SB]
U13  LD1117S50TR  [REG_SOT223-TAB]
U14  LD1117S33TR  [REG_SOT223-TAB]

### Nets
3V3: C42.1 JP5.1(COMMON) SB4.2
5V: C40.1 JP4.2 JP4.4 JP4.6 JP4.8 JP4.10 R25.1 U14.3(Vin)
5V_ARD: C39.1 JP4.3 U13.2(Vout) U13.4(Tab)
5V_ST_LINK: JP4.1
5V_USB_CHARGER: JP4.9
5V_USB_FS: JP4.5
GND: C38.2 C39.2 C40.2 C41.2 C42.2 JP6.1(COMMON) JP6.2(NO) JP7.1(COMMON) JP7.2(NO) LD5.K U13.1(Gnd) U14.1(Gnd)
LDO_3V3: C41.1 SB4.1 U14.2(Vout) U14.4(Tab)
VDD_MCU: JP5.2(NO)
VIN: C38.1 U13.3(Vin)
NetLD5_A: LD5.A R25.2

Not connected (* = marked no-connect by the designer): JP4 7

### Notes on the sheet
- 5V  PWR SELECTION FROM EXTERNAL SOURCES
- (near LD5) +5V
- USB_OTG_FS Page4/11
- STLINK_V2-1 Page11/11
- (near JP4) 5V_VBAT
- 5V
- 3V3
- GND PROBE
- 5V_USB_FS
- 5V_USB_ST_LINK
- 5V_USB_CHARGER
- 5V_ARD
- MEMS Page6/11
- POWER SUPPLY Page8/11
- RF_Module Page5/11
- 5V / 800mA
- 5V INPUT PWR FROM ARDUINO
- From Arduino power pin
- NFC_SAFE Page7/11
- (near C38) 0603
- (near C39) 0603
- 3V3 / 800mA
- 3V3 PWR
- VIN
- VDDA
- VDD_MCU
- (near JP5) IDD
- (near C40) 0603
- (near C41) 0603
- (near JP5) Jumper to measure IDD of the MCU
- ARDUINO Page9/11
- MCU1&2 Page2&3/11
- Peripherals Page10/11
- Open solder bridge if Discovery is supplied
  from +3V3 of extension connector
- Designed by DiZiC

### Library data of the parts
C38-C42 = CAP_NPOL: Capacitor_not polarized
HW1-HW4 = Shunt 2.54mm: SHUNT 2.54mm BLACK; Manuf_1: SAMTEC; Manuf_Part_1: SNT-100-BK-G; Fitted: Manually; Ordered_By: Subcon
JP5-JP7 = TSW-102-07-x-S: as JP8 on sheet MB1297_STLINK_V2-1
LD5 = LED: Light-Emitting Diode
R25 = RES: Resistor
SB4 = Strap2: Solder Jumper; Solder: YES
U13 = LD1117S50TR: IC REG LDO 5V 0.8A SOT223; Manuf_1: STM; ECCN_US/EU: EAR99/NEC; Ref St: 9176133; Fitted: YES
U14 = LD1117S33TR: LOW DROP FIXED AND ADJUSTABLE POSITIVE VOLTAGE REGULATORS (3.3 Volts); Manuf_1: STM; ECCN_US/EU: EAR99/NEC; Fitted: YES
